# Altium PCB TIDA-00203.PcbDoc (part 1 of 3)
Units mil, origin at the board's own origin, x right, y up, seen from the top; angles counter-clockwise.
Board outline 2000 x 3000 mil, 4 copper layers (TOP LAYER, L2_GND-PLANE, L3_PWR-PLANE, BOTTOM LAYER), stack 90 mil thick; 187 components, 138 nets, 683 pads, 415 vias.
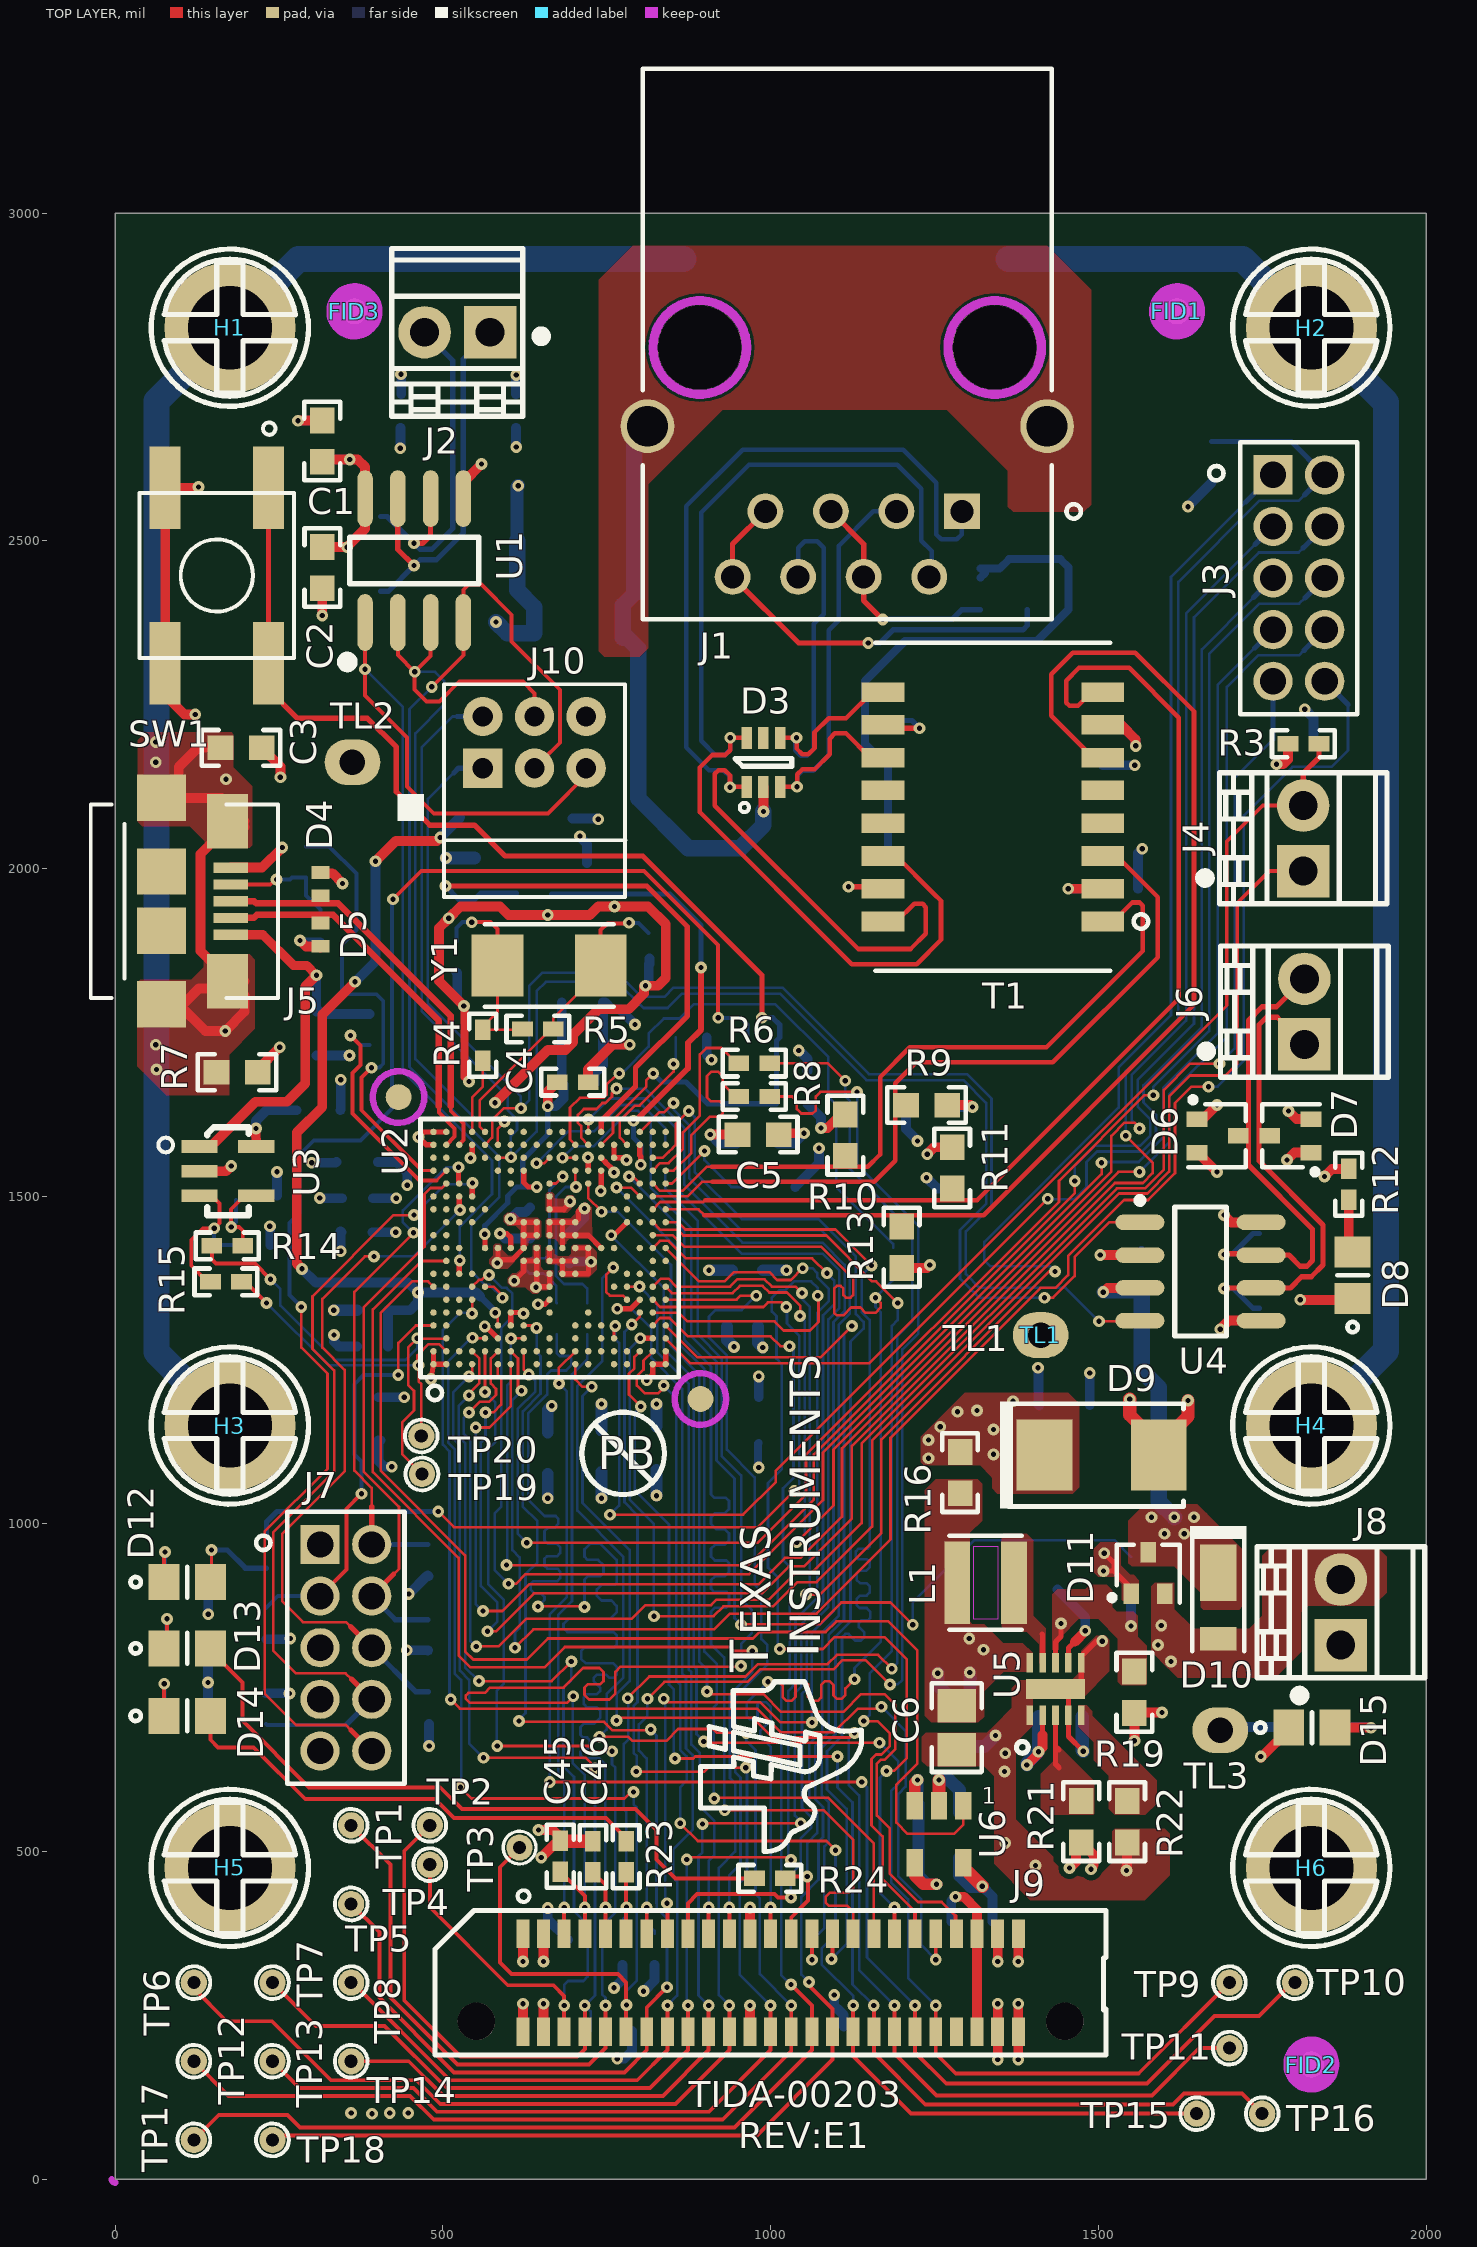
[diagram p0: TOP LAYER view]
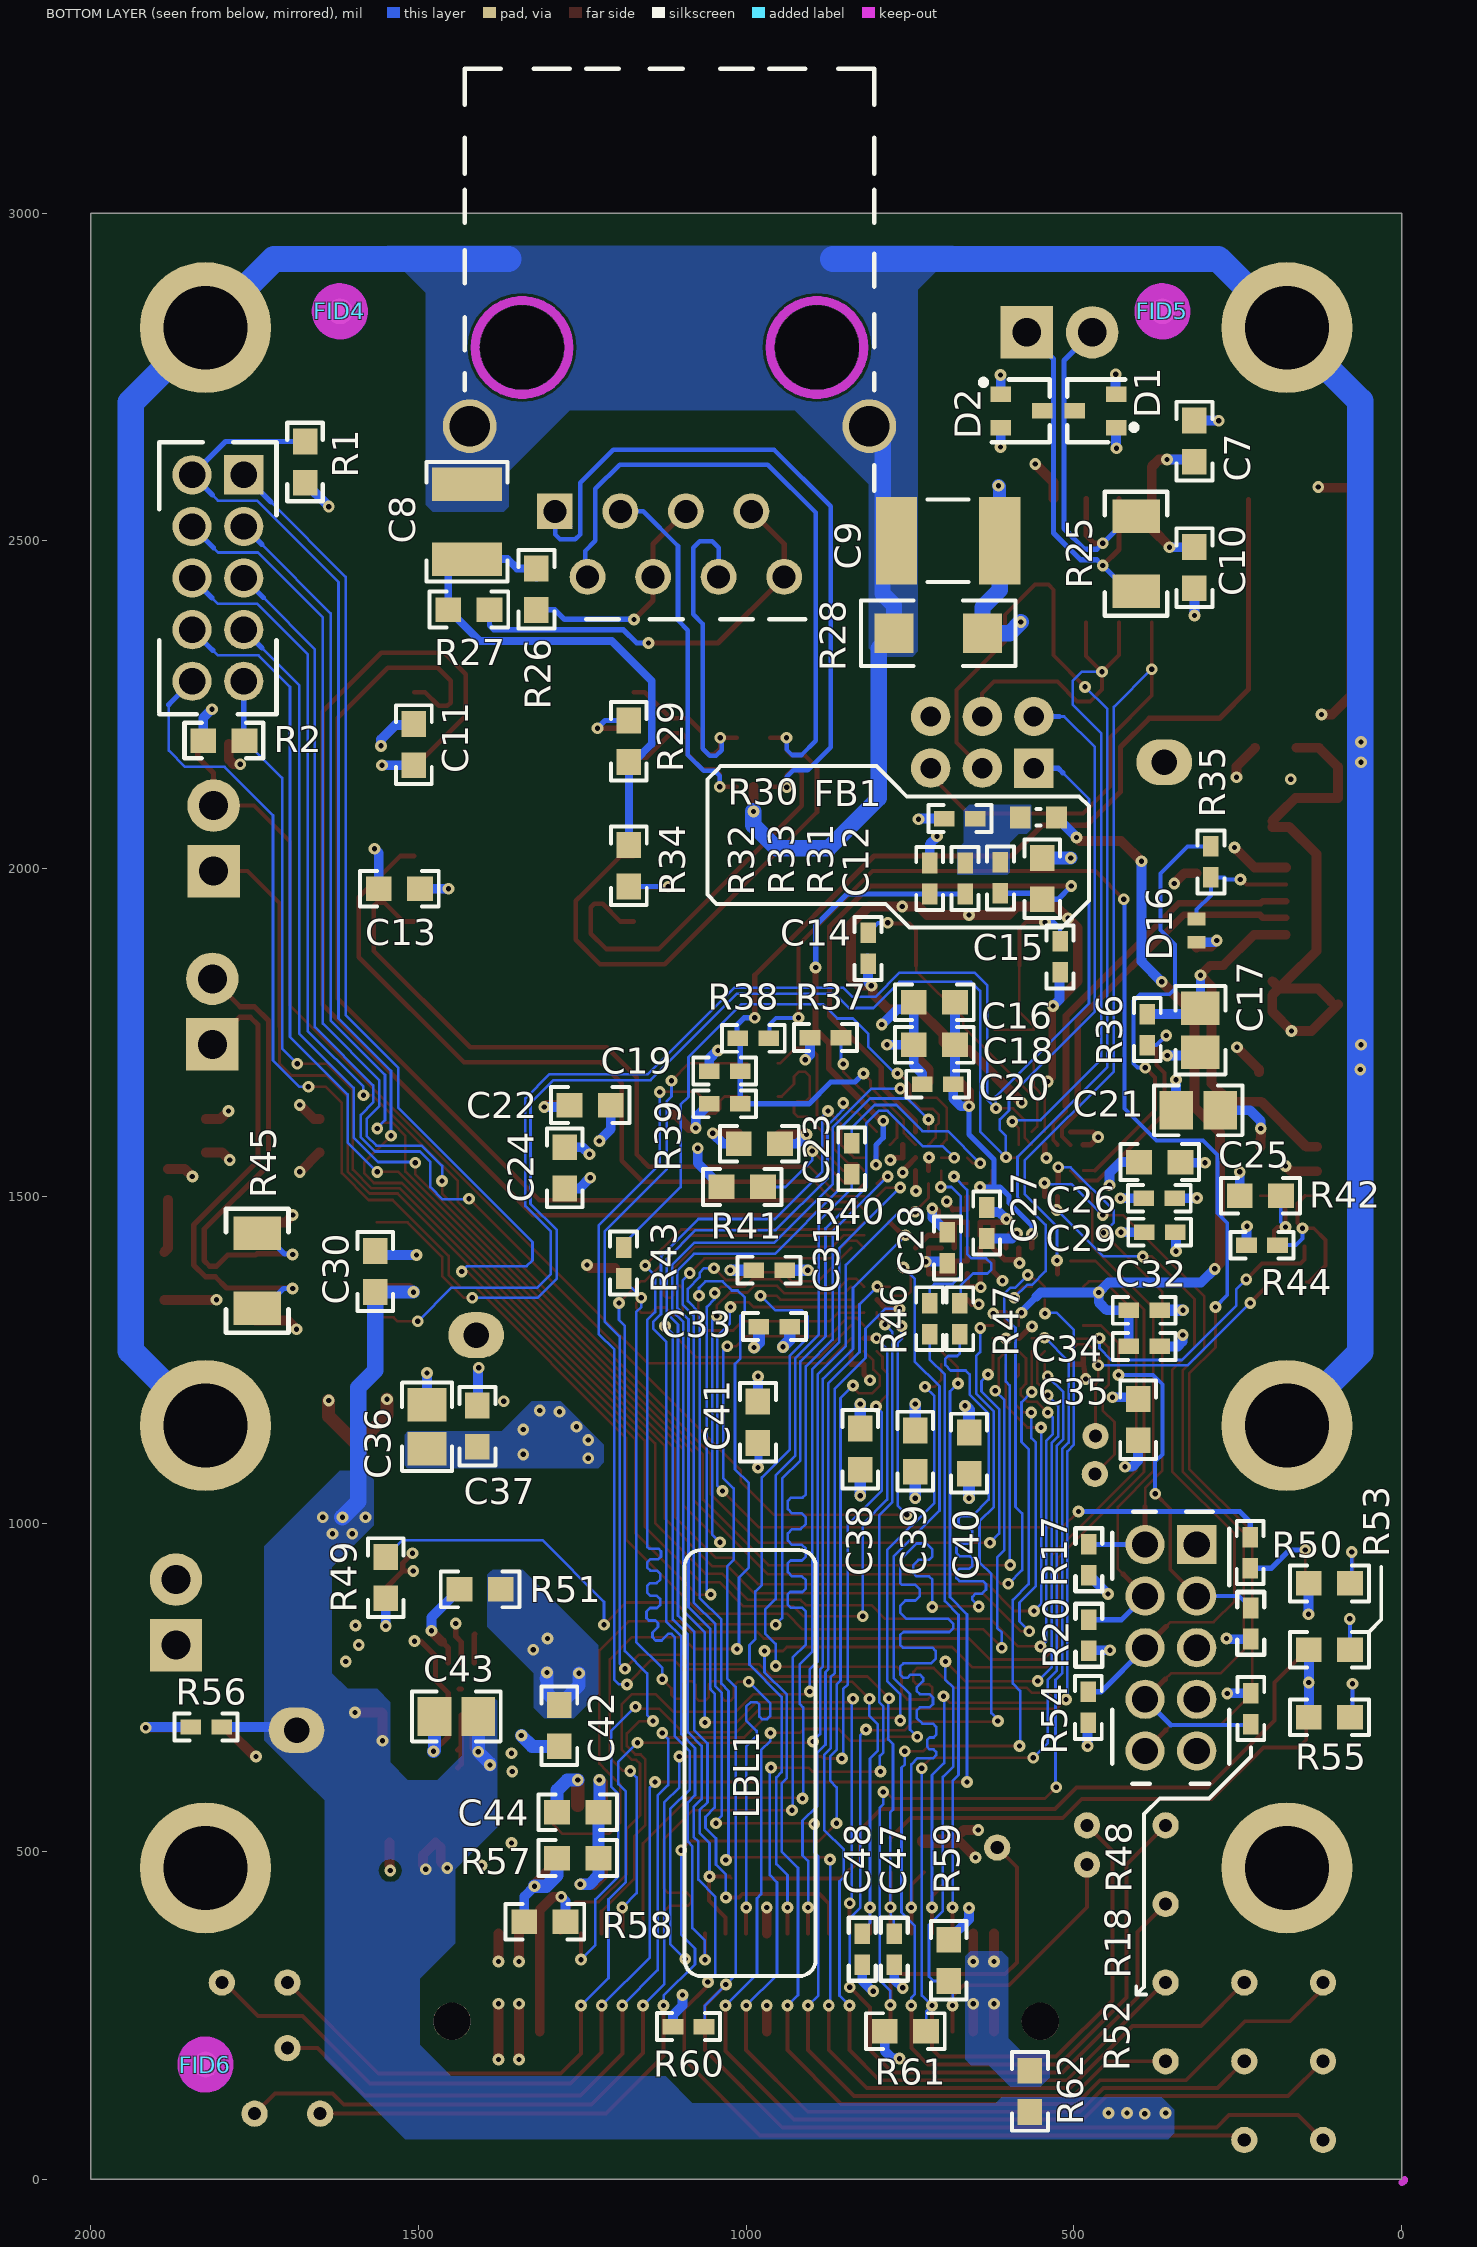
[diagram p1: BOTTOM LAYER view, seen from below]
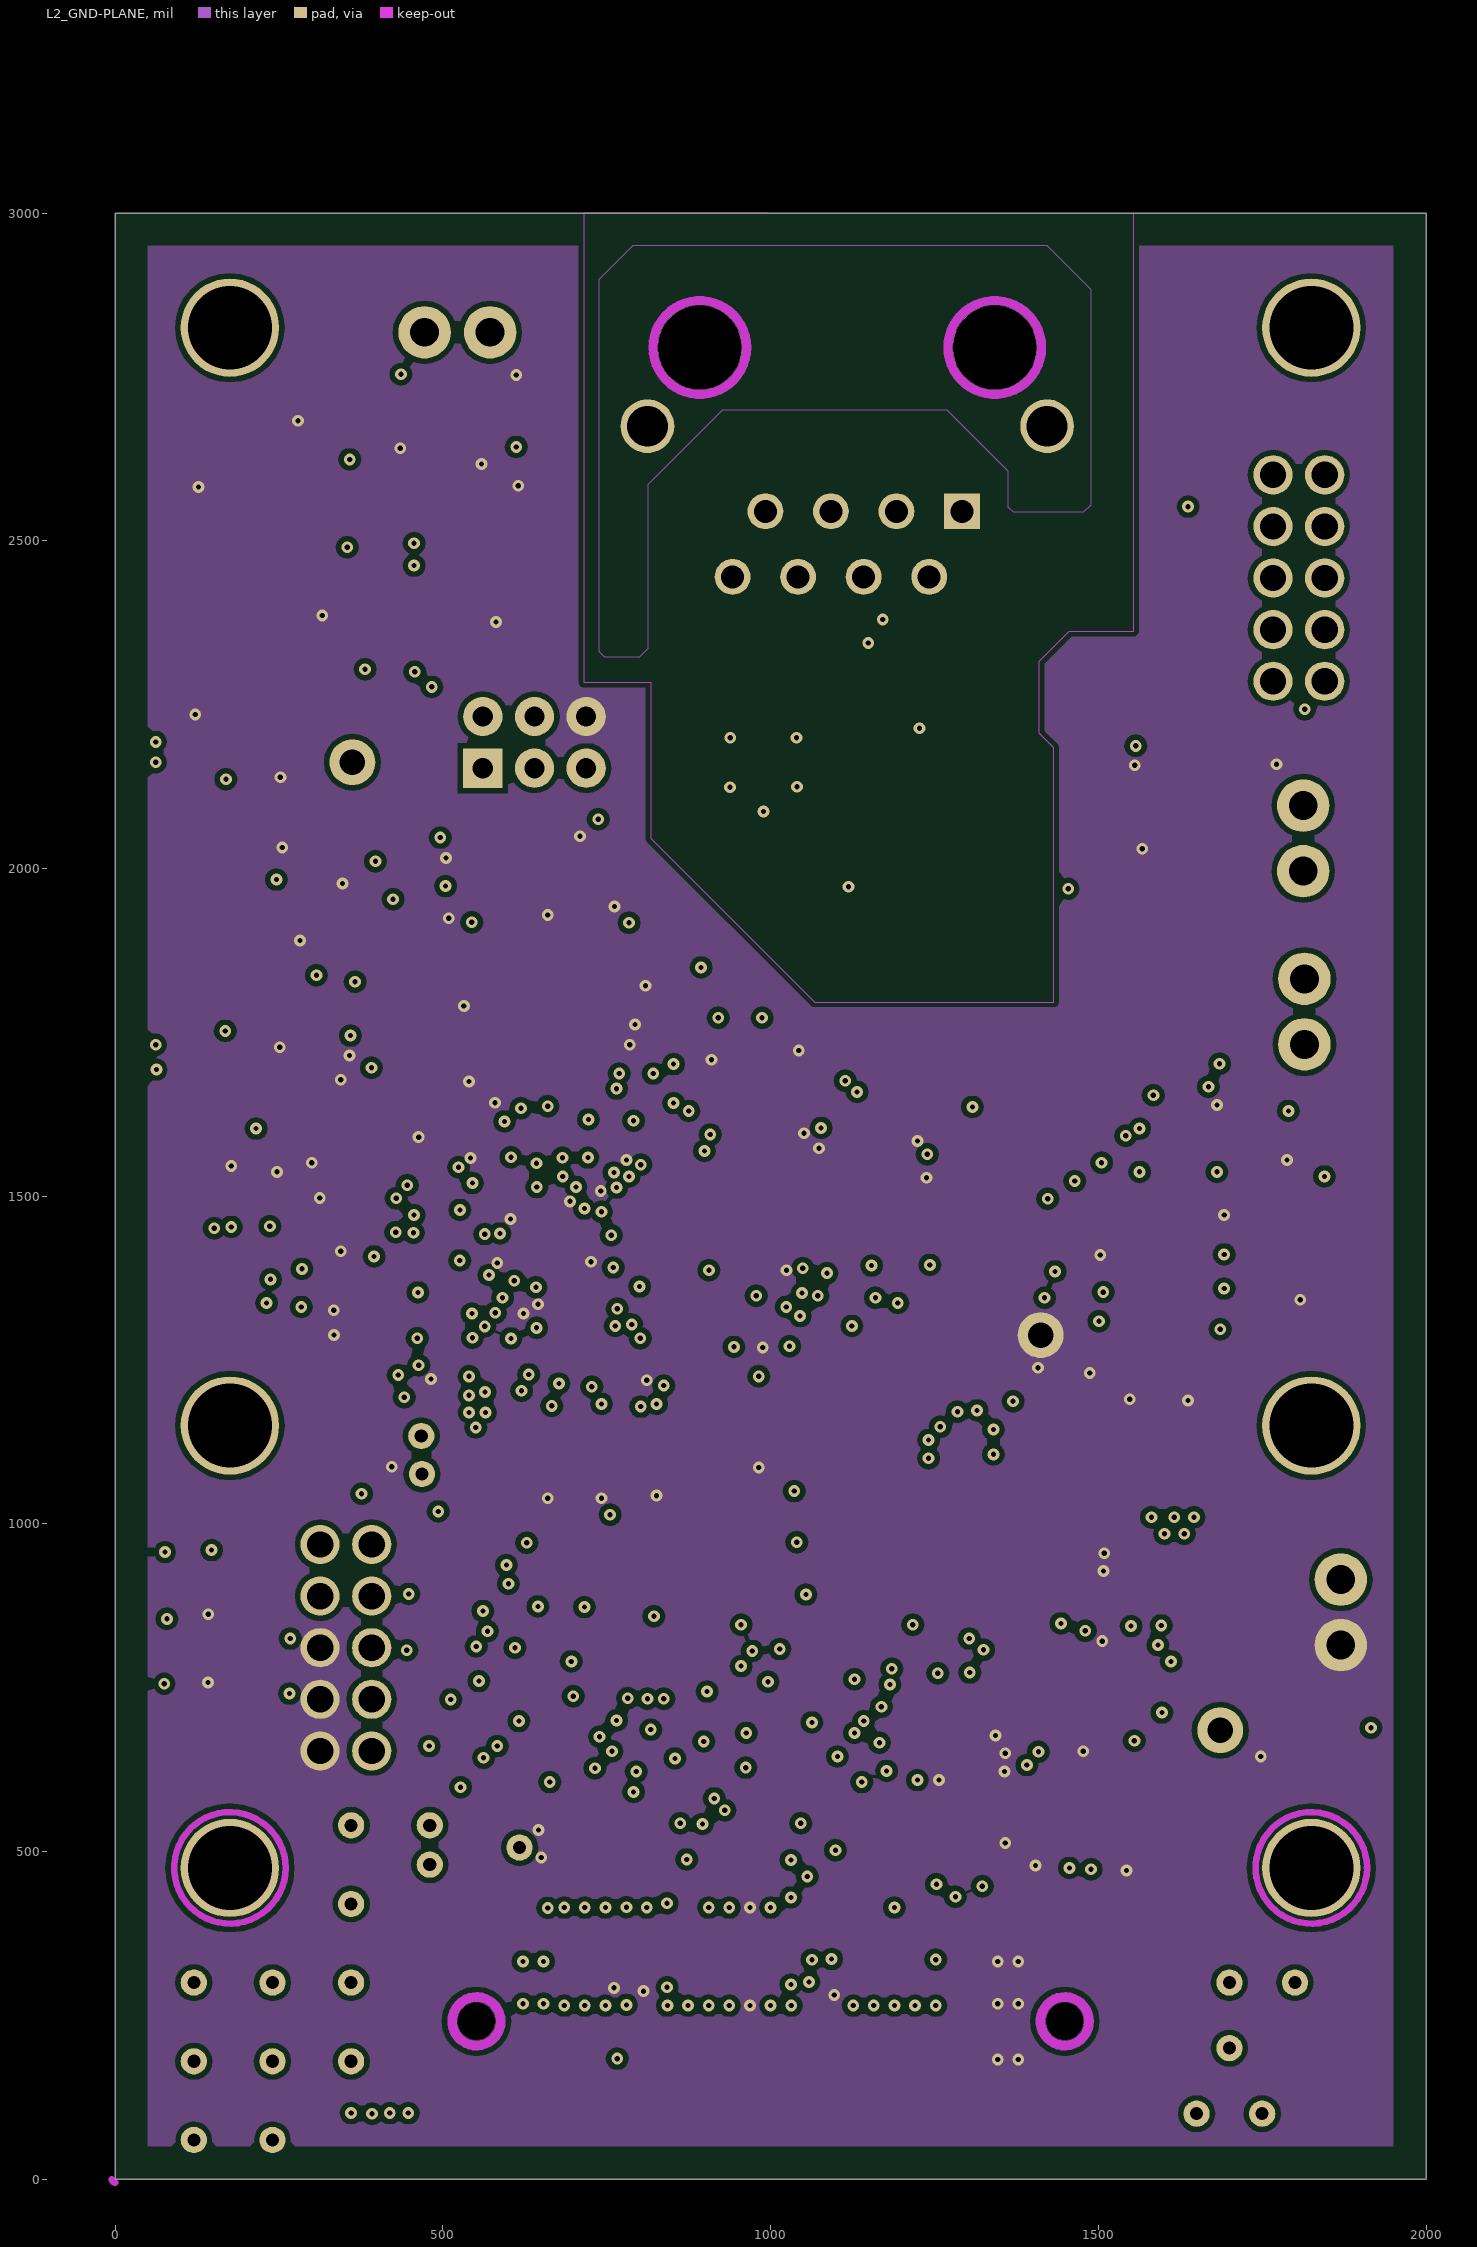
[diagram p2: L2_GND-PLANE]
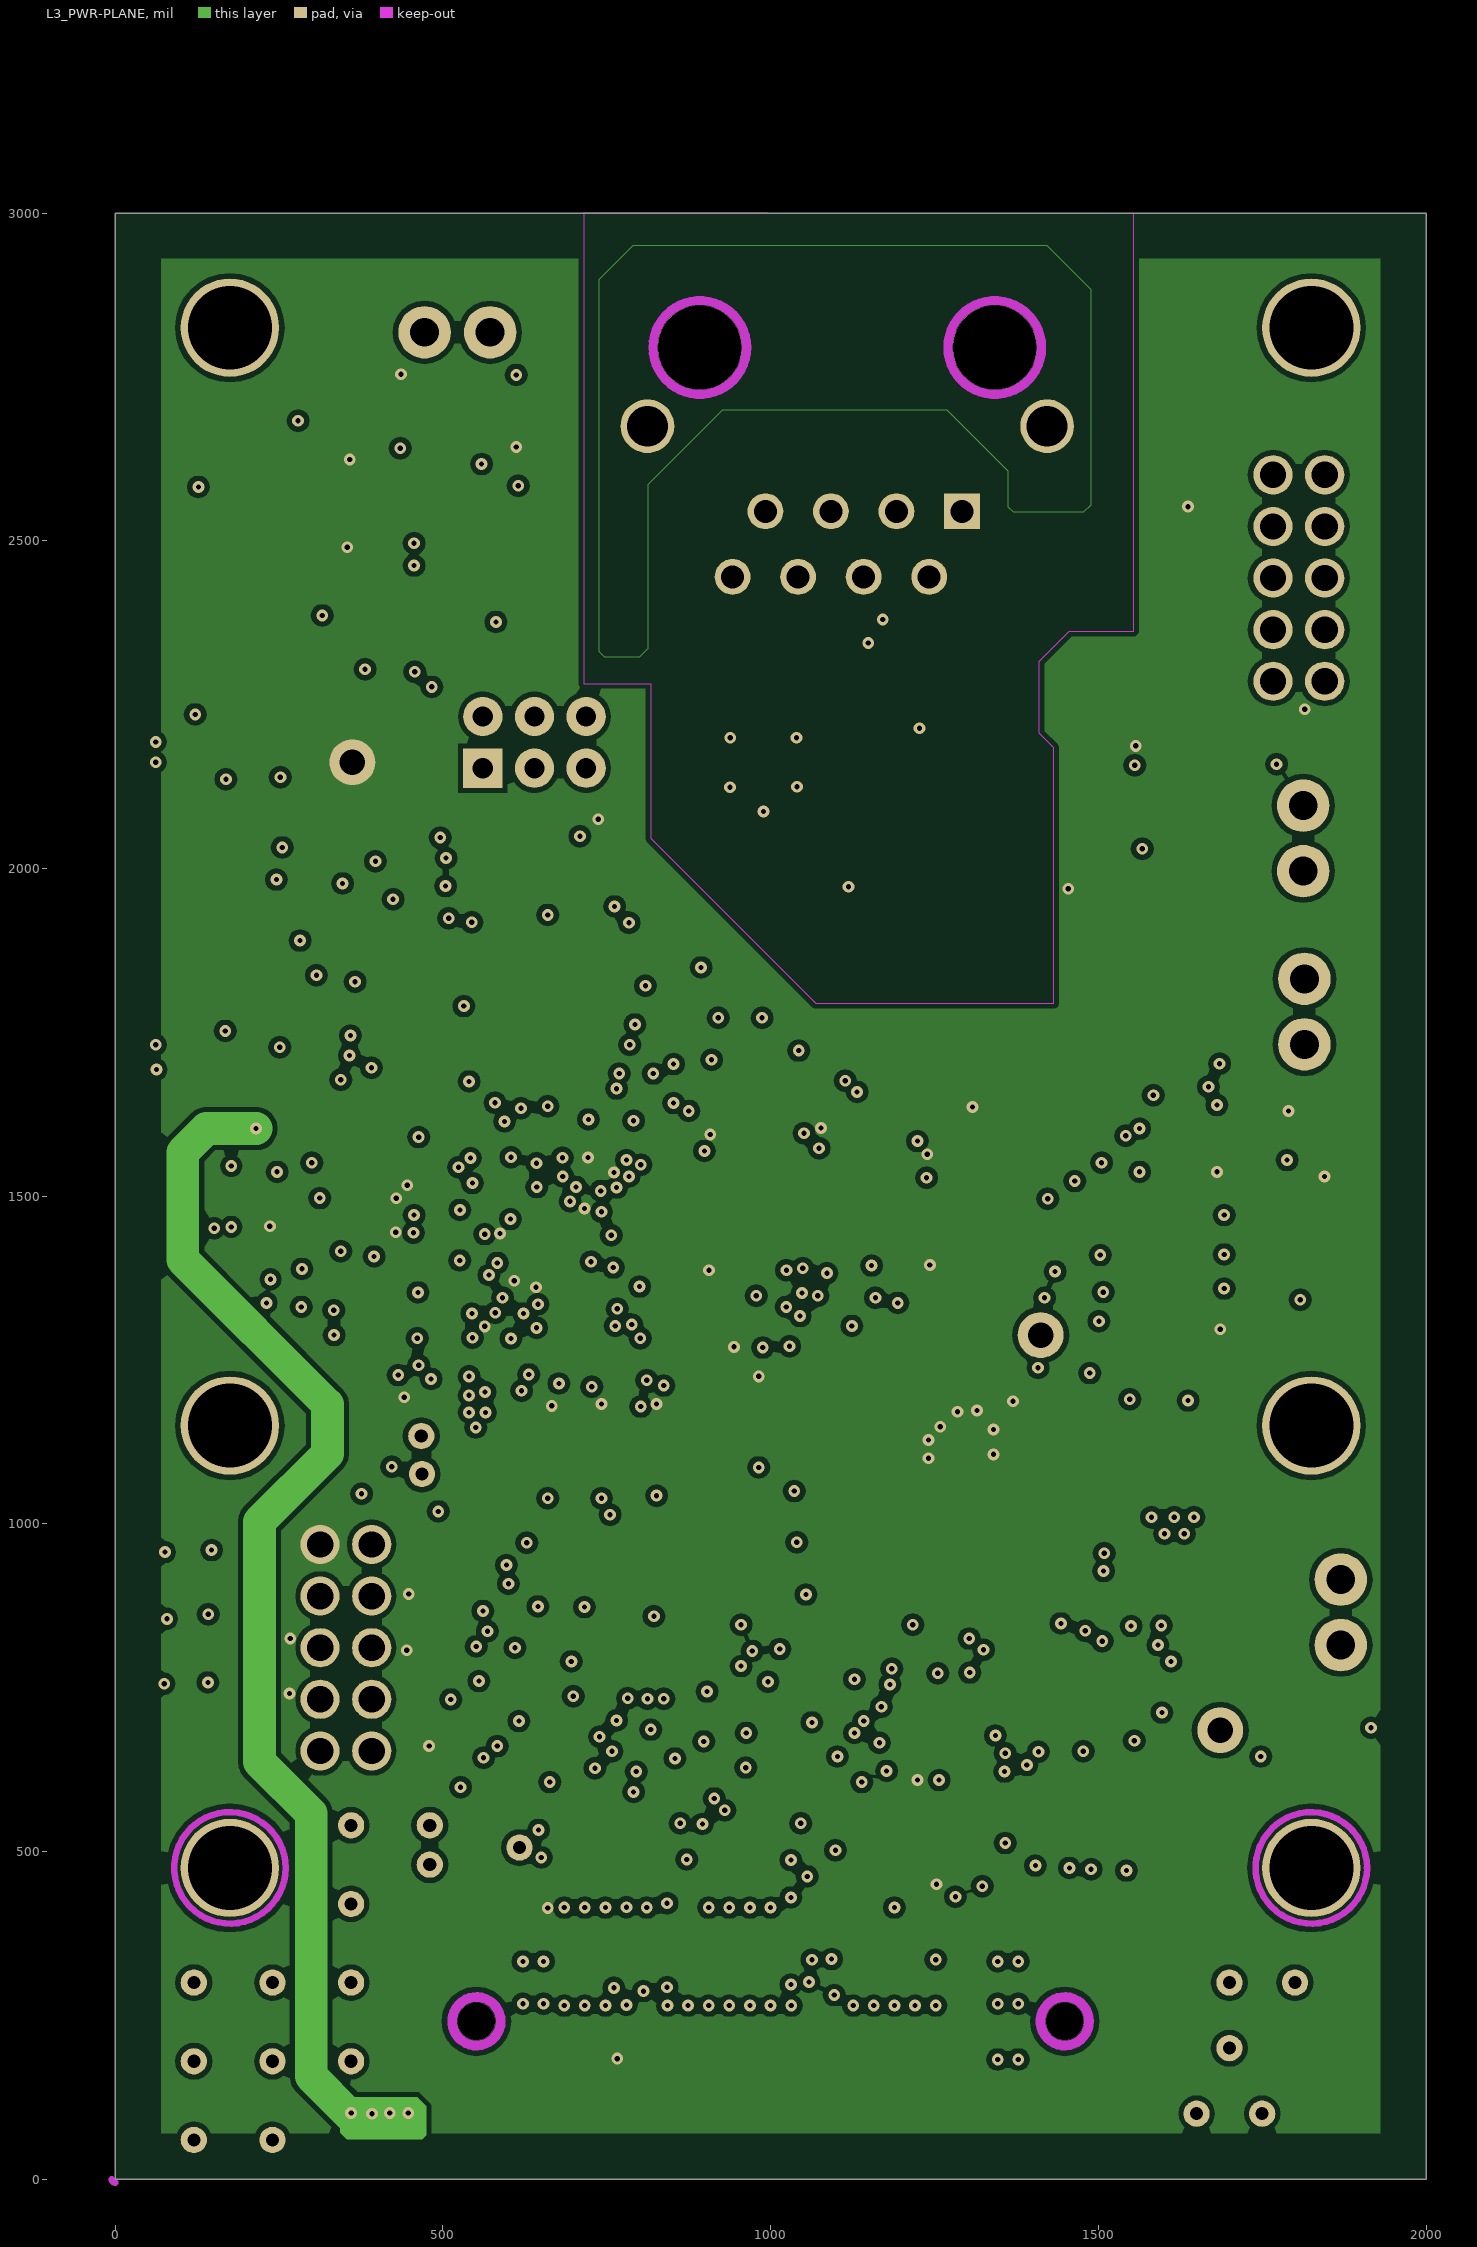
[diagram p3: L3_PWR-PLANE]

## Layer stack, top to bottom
TOP LAYER: signal copper 1.4
Dielectric: core 59.2, FR-4, Dk 4.8
L2_GND-PLANE: signal copper 1.4
Dielectric: prepreg 12.6, FR-4, Dk 4.8
L3_PWR-PLANE: signal copper 1.4
Dielectric: core 12.6, FR-4, Dk 4.8
BOTTOM LAYER: signal copper 1.4

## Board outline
0,0 2000,0 2000,3000 0,3000 0,0

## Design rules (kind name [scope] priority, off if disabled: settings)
Clearance L3 [OnLayer('L3_PWR-PLANE')] p1: gap=8
Clearance L2 [OnLayer('L2_GND-PLANE')] p2: gap=8
Clearance 5v [InNet('+5V')] p3: gap=8
Clearance Clearance_J4 [InPolygon vs InPadClass('J4-J6')] p4: gap=6
Clearance [All] p5: gap=4
Clearance DIFF_ETH [InNet('TX+_RJ45') vs InNet('TX-_RJ45')] p6: gap=16
Clearance "TRACE TO VIA" [IsVia vs IsTrack] p7: gap=4
Clearance "VIA TO TH PIN" [IsThruPin vs IsVia] p8: gap=10
Clearance "TRACE TO TRACE" [IsTrack vs IsTrack] p9: gap=4
Clearance "VIA TO VIA" [IsVia vs IsVia] p10: gap=8
Clearance "VIA 2 SMT PIN" [IsVia vs IsSMTPin] p11: gap=8
ComponentClearance "'Default' PADS rule_12" [All] p1: gap=6 collisioncheckmode=3 verticalgap=10 showdistances=FALSE
DiffPairsRouting DiffPair_ENO_TXDiffPairsRouting [InDifferentialPair ('EN0_TX')] p1: maxlimit=16 minlimit=16 mostfreqgap=16 maxuncoupledlength=500
DiffPairsRouting DiffPair_EN0_RXDiffPairsRouting [InDifferentialPair ('EN0_RX')] p2: maxlimit=16 minlimit=16 mostfreqgap=16 maxuncoupledlength=500
DiffPairsRouting DiffPair_RX_RJ45DiffPairsRouting [InDifferentialPair ('RX_RJ45')] p3: maxlimit=16 minlimit=16 mostfreqgap=16 maxuncoupledlength=500
DiffPairsRouting DiffPair_TX_RJ45DiffPairsRouting [InDifferentialPair ('TX_RJ45')] p4: maxlimit=16 minlimit=16 mostfreqgap=16 maxuncoupledlength=500
DiffPairsRouting [InDifferentialPair ('TX_RJ45')] p5: maxlimit=10 minlimit=10 mostfreqgap=10 maxuncoupledlength=500
DiffPairsRouting DiffPair_ETH_RXDiffPairsRouting [InDifferentialPair ('ETH_RX')] p6: maxlimit=16 minlimit=16 mostfreqgap=16 maxuncoupledlength=500
DiffPairsRouting DiffPair_ETHRX1DiffPairsRouting [InDifferentialPair ('ETH_RX')] p7: maxlimit=16 minlimit=16 mostfreqgap=16 maxuncoupledlength=500
DiffPairsRouting DiffPair_USB0DiffPairsRouting [InDifferentialPair ('USB0')] p8: maxlimit=7.5 minlimit=7.5 mostfreqgap=7.5 maxuncoupledlength=500
FlightTimeFalling "'Default' PADS rule_10" [All] p1: maximum=10.00
FlightTimeRising "'Default' PADS rule_9" [All] p1: maximum=10.00
HoleSize [All] p1: absolutevalues=TRUE maxlimit=150 minlimit=1 maxpercent=80.000 minpercent=20.000
Length TX [InNetClass('TX')] p1: maxlimit=1956 minlimit=1856
Length RX [InNetClass('RX')] p2: maxlimit=1667 minlimit=1567
MatchedLengths DiffPair_ENO_TXMatchedLengths [InDifferentialPair ('EN0_TX')] p1: tolerance=1000 checknetsindiffpair=TRUE checkdiffpairvsdiffpair=TRUE checkothers=TRUE
MatchedLengths DiffPair_EN0_RXMatchedLengths [InDifferentialPair ('EN0_RX')] p2: tolerance=1000 checknetsindiffpair=TRUE checkdiffpairvsdiffpair=TRUE checkothers=TRUE
MatchedLengths DiffPair_RX_RJ45MatchedLengths [InDifferentialPair ('RX_RJ45')] p3: tolerance=1000 checknetsindiffpair=TRUE checkdiffpairvsdiffpair=TRUE checkothers=TRUE
MatchedLengths DiffPair_TX_RJ45MatchedLengths [InDifferentialPair ('TX_RJ45')] p4: tolerance=1000 checknetsindiffpair=TRUE checkdiffpairvsdiffpair=TRUE checkothers=TRUE
MatchedLengths [InDifferentialPair ('TX_RJ45')] p5: tolerance=1000 checknetsindiffpair=TRUE checkdiffpairvsdiffpair=TRUE checkothers=TRUE
MaxMinImpedance "'Default' PADS rule_8" [All] p1: minimum=50.00 maximum=150.0
ParallelSegment "'Default' PADS rule_7" [All] p1: limit=1000 gap=200
ParallelSegment "'Default' PADS rule_6" [All] p2: limit=1000 gap=200
PlaneClearance "'Net' PADS rule_20" [InNet('GND')] p1: clearance=10
PlaneClearance "'Default' PADS rule_14" [All] p2: clearance=10
PlaneConnect "Power Plane Connect Style - pads with no thermal" [(Name='A1-1') Or (Name='A2-1') Or (Name='A3-1') Or (Name='A4-1') Or (Name='A5-1') Or (Name='A6-1') Or (Name='A7-1') Or (Name='A8-1') Or (Name='J15-5') Or (Name='J15-6') Or (Name='J19-21') Or (Name='J19-22') Or (Name='J27-2') Or (Name='J27-4') Or (Name='J28-2') Or (Name='J30-B4') Or (Name='J31-21') Or (Name='J31-22') Or (Name='J32-11') Or (Name='J32-12') Or (Name='J38-11') Or (Name='J38-12') Or (Name='J38-13')] p1: planeconnectstyle=NoConnect reliefexpansion=20 reliefentries=4 reliefconductorwidth=10 reliefairgap=10 // PAD - No Thermal Connect Rule
PlaneConnect "Power Plane Connect Style - from global settings" [All] p2: planeconnectstyle=Relief reliefexpansion=20 reliefentries=2 reliefconductorwidth=8 reliefairgap=10
PolygonConnect PolygonConnect_16 [All] p1: connectstyle=Direct reliefconductorwidth=10 reliefentries=4 polygonreliefangle="90 Angle" airgapwidth=10
PolygonConnect PolygonConnect_15 [All] p2: connectstyle=Direct reliefconductorwidth=10 reliefentries=4 polygonreliefangle="90 Angle" airgapwidth=10
PolygonConnect PolygonConnect_14 [All vs IsNamedPolygon('Bottom Layer-No Net 1')] p3: connectstyle=Direct reliefconductorwidth=10 reliefentries=4 polygonreliefangle="90 Angle" airgapwidth=10
PolygonConnect PolygonConnect_13 [All vs IsNamedPolygon('Top Layer-No Net 2')] p4: connectstyle=Direct reliefconductorwidth=10 reliefentries=4 polygonreliefangle="90 Angle" airgapwidth=10
PolygonConnect PolygonConnect_12 [All vs IsNamedPolygon('Top Layer-No Net 2')] p5: connectstyle=Direct reliefconductorwidth=10 reliefentries=4 polygonreliefangle="90 Angle" airgapwidth=10
PolygonConnect PolygonConnect_11 [All vs IsNamedPolygon('Bottom Layer-No Net 2')] p6: connectstyle=Direct reliefconductorwidth=10 reliefentries=4 polygonreliefangle="90 Angle" airgapwidth=10
PolygonConnect PolygonConnect_10 [All vs IsNamedPolygon('Bottom Layer-No Net 2')] p7: connectstyle=Direct reliefconductorwidth=10 reliefentries=4 polygonreliefangle="90 Angle" airgapwidth=10
PolygonConnect PolygonConnect_9 [All vs IsNamedPolygon('Bottom Layer-No Net 2')] p8: connectstyle=Direct reliefconductorwidth=10 reliefentries=4 polygonreliefangle="90 Angle" airgapwidth=10
PolygonConnect PolygonConnect_8 [All vs IsNamedPolygon('Top Layer-No Net 2')] p9: connectstyle=Direct reliefconductorwidth=10 reliefentries=4 polygonreliefangle="90 Angle" airgapwidth=10
PolygonConnect PolygonConnect_6 [All vs IsNamedPolygon('Top Layer-No Net 1')] p10: connectstyle=Direct reliefconductorwidth=10 reliefentries=4 polygonreliefangle="90 Angle" airgapwidth=10
PolygonConnect PolygonConnect_5 [All vs IsNamedPolygon('Top Layer-No Net')] p11: connectstyle=Direct reliefconductorwidth=10 reliefentries=4 polygonreliefangle="90 Angle" airgapwidth=10
PolygonConnect PolygonConnect_4 [All vs IsNamedPolygon('Bottom Layer-No Net 1')] p12: connectstyle=Direct reliefconductorwidth=10 reliefentries=4 polygonreliefangle="90 Angle" airgapwidth=10
PolygonConnect PolygonConnect_3 [All vs IsNamedPolygon('Bottom Layer-No Net')] p13: connectstyle=Direct reliefconductorwidth=10 reliefentries=4 polygonreliefangle="90 Angle" airgapwidth=10
PolygonConnect PolygonConnect_2 [All vs IsNamedPolygon('Bottom Layer-No Net')] p14: connectstyle=Direct reliefconductorwidth=10 reliefentries=4 polygonreliefangle="90 Angle" airgapwidth=10
PolygonConnect PolygonConnect_1 [All vs IsNamedPolygon('Bottom Layer-No Net')] p15: connectstyle=Direct reliefconductorwidth=10 reliefentries=4 polygonreliefangle="90 Angle" airgapwidth=10
PolygonConnect [All] p16: connectstyle=Relief reliefconductorwidth=10 reliefentries=4 polygonreliefangle="90 Angle" airgapwidth=10
RoutingVias [All] p1: holewidth=8 width=18 viastyle="Through Hole" minholewidth=8 minwidth=18 maxholewidth=8 maxwidth=18
SMDToCorner [All] p1: distance=40000
SMDToPlane [All] p1: distance=40000
SilkscreenOverComponentPads [All] p1: minsilkscreentomaskgap=10
SolderMaskExpansion [All] p1: expansion=2
Width DiffPair_ENO_TXWidth [InDifferentialPair('EN0_TX')] p1: maxlimit=7 minlimit=4 preferedwidth=7
Width DiffPair_EN0_RXWidth [InDifferentialPair('EN0_RX')] p2: maxlimit=7 minlimit=4 preferedwidth=7
Width DiffPair_RX_RJ45Width [InDifferentialPair('RX_RJ45')] p3: maxlimit=7 minlimit=4 preferedwidth=7
Width DiffPair_TX_RJ45Width [InDifferentialPair('TX_RJ45')] p4: maxlimit=7 minlimit=4 preferedwidth=7
Width Width_3 [InDifferentialPair('TX_RJ45')] p5: maxlimit=10 minlimit=10 preferedwidth=10
Width DiffPair_ETH_RXWidth [InDifferentialPair('ETH_RX')] p6: maxlimit=7 minlimit=7 preferedwidth=7
Width DiffPair_ETHRX1Width [InDifferentialPair('ETH_RX')] p7: maxlimit=7 minlimit=7 preferedwidth=7
Width DiffPair_USB0Width [InDifferentialPair('USB0')] p8: maxlimit=10 minlimit=10 preferedwidth=10
Width Width_2 [InNet('GND')] p9: maxlimit=50 minlimit=8 preferedwidth=15
Width Width_1 [InNet('3.3V')] p10: maxlimit=25 minlimit=8 preferedwidth=15
Width [All] p11: maxlimit=100 minlimit=4 preferedwidth=4
22 further rules are at their usual default settings.

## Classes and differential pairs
component class Pg4_10_100_ETHERNET_USB: C3 C8 C9 C11 C13 C17 C21 C22 C24 D3 D4 D5 D12 D13 D14 D16 J1 J5 R7 R9 R10 R11 R13 R14 R15 R23 R24 R26 R27 R28 R29 R34 R35 R36 R41 R42 R44 R48 R50 R53 R55 T1 TP19 TP20 U3
pad class J4-J6: J2-1 J2-2 J4-1 J4-2 J6-1 J6-2 R42-1 R42-2 R44-1 R44-2
net class TX_U-C: NetR6_1 NetR8_1 NetR40_1 NetR47_1
component class Label: LBL1
component class AssemblyNote: ZZ1 ZZ2 ZZ3 ZZ4
component class Pg9_Hardware_ANSI-B: FID1 FID2 FID3 FID4 FID5 FID6 H1 H2 H3 H4 H5 H6 LBL1 ZZ1 ZZ2 ZZ3 ZZ4
component class Pg5_CAN_RS485: C1 C2 C7 C10 C30 D1 D2 D6 D7 J2 J6 J10 R25 R45 U1 U4
component class FiducialMark: FID1 FID2 FID3 FID4 FID5 FID6
component class "Mounting Holes": H1 H2 H3 H4 H5 H6
component class Pg7_POWER_SUPPLY: C6 C36 C37 C42 C43 C101 D8 D9 D15 L1 R12 R16 R19 R21 R22 R49 R51 R56 TL1 TL2 TL3 U5
component class Pg6_MII_RMII_INTERFACE: C44 D10 D11 J8 J9 R57 R58 R62 TP1 TP2 TP3 TP4 TP5 TP6 TP7 TP8 TP9 TP10 TP11 TP12 TP13 TP14 TP15 TP16 TP17 TP18 U6
component class Pg3_MICROCONTROLLER: C4 C5 C12 C14 C15 C16 C18 C19 C20 C23 C25 C26 C27 C28 C29 C31 C32 C33 C34 C35 C38 C39 C40 C41 C45 C46 C47 C48 FB1 R1 R2 R3 R4 R5 R6 R8 R30 R31 R32 R33 R37 R38 R39 R40 R43 R46 R47 R59 R60 R61 R97 SW1 U2 Y1
component class Pg8_SPARE_AND_DEBUG: J3 J4 J7 R17 R18 R20 R52 R54
net class TX: TX_CLK TXD0 TXD1 TXD2 TXD3
net class RX: RX_CLK RXD0 RXD1 RXD2 RXD3
differential pair TX_RJ45: +TX+_RJ45 -TX-_RJ45
differential pair RX_RJ45: +RX+_RJ45 -RX-_RJ45
differential pair EN0_RX: +EN0RX+ -EN0RX-
differential pair EN0_TX: +EN0TX+ -EN0TX-

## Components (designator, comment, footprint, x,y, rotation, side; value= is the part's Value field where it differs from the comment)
C1 "C0603C106M9PACTU" 0603 316,2652 r90 top (schematic designator C93)
C2 "GRM188R61C104KA01D" 0603 316,2459 r270 top (schematic designator C95)
C3 "CAPC0603" 0603 192,2184 r180 top (schematic designator C30)
C4 "CAPC0603" 0402 698,1674 r0 top (schematic designator C61)
C5 "CAPC0603" 0603 981,1594 r0 top (schematic designator C39)
C6 "CAPC0805" 0805 1284,689 r270 top (schematic designator C2)
C7 "GRM188R61C104KA01D" 0603 316,2652 r90 bottom (schematic designator C94)
C8 "CAPC1210" 1210 1426,2529 r90 bottom (schematic designator C90)
C9 "CAPC0603" 1812 692,2500 r180 bottom (schematic designator C38)
C10 "GRM188R61C104KA01D" 0603 316,2459 r270 bottom (schematic designator C96)
C11 "CAPC0603" 0603 1507,2189 r270 bottom (schematic designator C66)
C12 "CAPC0603" 0603 548.21,1984.34 r90 bottom (schematic designator C70)
C13 "CAPC0603" 0603 1529,1969 r0 bottom (schematic designator C40)
C14 "GRM1555C1H330JA01D" 0402 814,1878 r90 bottom (schematic designator C25)
C15 "GRM1555C1H330JA01D" 0402 521,1865 r270 bottom (schematic designator C23)
C16 "CAPC0603" 0603 712.72,1795.79 r0 bottom (schematic designator C53)
C17 "CAPC0805" 0805 307,1753 r270 bottom
C18 "CAPC0603" 0603 712.72,1730.79 r0 bottom (schematic designator C55)
C19 "CAPC0402" 0402 1032.72,1690.79 r0 bottom (schematic designator C99)
C20 "CAPC0402" 0402 707.72,1670.79 r0 bottom (schematic designator C57)
C21 "CAPC0805" 0805 310,1631 r0 bottom (schematic designator C19)
C22 "CAPC0603" 0603 1238,1639 r180 bottom (schematic designator C62)
C23 "CAPC0603" 0603 979.72,1579.79 r0 bottom (schematic designator C16)
C24 "CAPC0603" 0603 1277,1543 r270 bottom (schematic designator C65)
C25 "CAPC0603" 0603 369,1552 r180 bottom (schematic designator C54)
C26 "CAPC0402" 0402 369.72,1496.79 r180 bottom (schematic designator C59)
C27 "CAPC0603" 0402 633,1459 r90 bottom (schematic designator C63)
C28 "CAPC0603" 0402 693,1421 r270 bottom (schematic designator C64)
C29 "CAPC0402" 0402 369,1445 r180 bottom (schematic designator C60)
C30 "06033C104JAT2A" 0603 1566,1385 r270 bottom (schematic designator C91)
C31 "CAPC0402" 0402 965,1387 r0 bottom (schematic designator C22)
C32 "CAPC0402" 0402 392.72,1325.79 r180 bottom (schematic designator C18)
C33 "CAPC0402" 0402 957,1301 r0 bottom (schematic designator C56)
C34 "CAPC0402" 0402 392.72,1270.79 r180 bottom (schematic designator C58)
C35 "CAPC0603" 0603 402,1159 r270 bottom (schematic designator C29)
C36 "CAPC0805" 0805 1487,1148 r90 bottom (schematic designator C101)
C37 "CAPC0603" 0603 1410,1149 r90 bottom (schematic designator C102)
C38 "CAPC0603" 0603 826,1114 r270 bottom (schematic designator C28)
C39 "CAPC0603" 0603 742,1111 r270 bottom (schematic designator C33)
C40 "CAPC0603" 0603 660,1108 r270 bottom (schematic designator C52)
C41 "CAPC0603" 0603 982,1155 r270 bottom (schematic designator C67)
C42 "CAPC0603" 0603 1285,692 r270 bottom (schematic designator C100)
C43 "CAPC0805" 0805 1442.1,706.1 r0 bottom (schematic designator C4)
C44 "06033C104JAT2A" 0603 1257,560 r0 bottom (schematic designator C92)
C45 "GRM1555C1H330JA01D" 0402 679,493 r270 top
C46 "GRM1555C1H330JA01D" 0402 729,492 r270 top
C47 "GRM1555C1H330JA01D" 0402 774,351 r90 bottom
C48 "GRM1555C1H330JA01D" 0402 823,351 r90 bottom
D1 "DESD1P0RFW-7" SOT-323 467,2698 r0 bottom (schematic designator D21)
D2 "DESD1P0RFW-7" SOT-323 580,2698 r180 bottom (schematic designator D20)
D3 "TPD4E1U06DCK" DCK0006A_N 989,2161.91 r90 top
D4 "B72590D0050H160" RESC0402N 313,1976 r90 top (schematic designator D6)
D5 "B72590D0050H160" RESC0402N 313,1899 r270 top
D6 "DESD1P0RFW-7" SOT-323 1682,1592 r0 top (schematic designator D18)
D7 "DESD1P0RFW-7" SOT-323 1793,1592 r180 top (schematic designator D19)
D8 "LED-0805" DIOC0805N 1888,1379 r90 top (schematic designator D10)
D9 "1SMB5915BT3G" SMB 1505,1105 r0 top (schematic designator D23)
D10 "DFLS1200-7" powerDI123 1683,875 r270 top (schematic designator D17)
D11 "DESD1P0RFW-7" SOT-323 1576,925 r90 top (schematic designator D22)
D12 "LED-0805" DIOC0805N 110,911 r0 top (schematic designator D8)
D13 "LED-0805" DIOC0805N 110,810 r0 top (schematic designator D16)
D14 "LED-0805" DIOC0805N 110,707 r0 top (schematic designator D15)
D15 "LED-0805" DIOC0805N 1826,689 r0 top (schematic designator D9)
D16 "B72590D0050H160" RESC0402N 313,1905 r270 bottom (schematic designator D7)
FB1 "1000 OHM" 0603L 554,2078 r180 bottom
FID1 "Fiducial" Fiducial10-20 1620,2850 r90 top
FID2 "Fiducial" Fiducial10-20 1825,175 r0 top
FID3 "Fiducial" Fiducial10-20 365,2850 r0 top
FID4 "Fiducial" Fiducial10-20 1620,2850 r180 bottom (schematic designator FID3)
FID5 "Fiducial" Fiducial10-20 365,2850 r180 bottom (schematic designator FID1)
FID6 "Fiducial" Fiducial10-20 1825,175 r180 bottom (schematic designator FID2)
H1 "NY PMS 440 0025 PH" MH3.2_H5_W6_KO8_STARHEAD#1 175,2825 r0 top locked
H2 "NY PMS 440 0025 PH" MH3.2_H5_W6_KO8_STARHEAD#2 1825,2825 r0 top locked
H3 "NY PMS 440 0025 PH" MH3.2_H5_W6_KO8_STARHEAD#2 175,1150 r0 top locked (schematic designator H13)
H4 "NY PMS 440 0025 PH" MH3.2_H5_W6_KO8_STARHEAD#2 1825,1150 r0 top locked (schematic designator H14)
H5 "NY PMS 440 0025 PH" MH3.2_H5_W6_KO8_STARHEAD#2 175,475 r0 top locked (schematic designator H3)
H6 "NY PMS 440 0025 PH" MH3.2_H5_W6_KO8_STARHEAD#2 1825,475 r0 top locked (schematic designator H4)
J1 "RJ45_NOMAG_NOLED" TE_6116526-1 1117,2800 r180 top locked
J2 "CON-OSTVN02A150" CN2_MTB_P100_PD80_D1.1_S5.54X6.5_STACK 522,2818 r180 top (schematic designator J38)
J3 "HEADER_2041501" "HDR2X5 _2MM" 1806,2443 r0 top
J4 "CON-OSTVN02A150" CN2_MTB_P100_PD80_D1.1_S5.54X6.5_STACK 1812.68,2045.92 r90 top (schematic designator J35)
J5 "ZX62R-AB-5P" CON-USB-MICRO-REV 71,1950 r0 top (schematic designator J24)
J6 "CON-OSTVN02A150" CN2_MTB_P100_PD80_D1.1_S5.54X6.5_STACK 1814.49,1781.49 r90 top (schematic designator J37)
J7 "HEADER_2041501" "HDR2X5 _2MM" 352,811 r0 top
J8 "CON-OSTVN02A150" CN2_MTB_P100_PD80_D1.1_S5.54X6.5_STACK 1870,865 r90 top (schematic designator J36)
J9 "ERM8-025-05.0-L-DV-K-TR" SAMTEC_ERM8-025-05_0-L-DV-K-TR 1000,300 r0 top locked (schematic designator J40)
J10 "HEADER_TMM-103-01-G-D-RA" HEADER_TMM-103[2X] 561,2153 r0 top
L1 "IND-WE-7440" IND_744029100 1328,910 r180 top
LBL1 "Size: 0.65\" x 0.20 \"" Label_650x200 994,635 r90 bottom
R1 "RESC0603" 0603 1673,2620 r90 bottom (schematic designator R91)
R2 "RESC0603" 0603 1797,2195 r180 bottom (schematic designator R87)
R3 "CRCW04022K20JNED" 0402 1813,2190 r0 top (schematic designator R94)
R4 "RESC0402" 0402 561,1730 r270 top (schematic designator R33)
R5 "CRCW04021M00JNED" 0402 645,1755 r180 top (schematic designator R92)
R6 "RESC0402" 0402 975,1703 r0 top (schematic designator R81)
R7 "RESC0603" 0603 186,1689 r0 top (schematic designator R36)
R8 "RESC0402" 0402 975,1652 r0 top (schematic designator R82)
R9 "RESC0603" 0603 1238,1639 r180 top (schematic designator R41)
R10 "RESC0603" 0603 1114,1593 r270 top (schematic designator R42)
R11 "RESC0603" 0603 1277,1543 r270 top (schematic designator R37)
R12 "RESC0402" 0402 1882,1518 r270 top (schematic designator R49)
R13 "RESC0603" 0603 1200,1422 r90 top (schematic designator R40)
R14 "CRCW040233R0JNED" 0402 171,1424 r180 top (schematic designator R85)
R15 "CRCW040233R0JNED" 0402 169,1369 r0 top (schematic designator R86)
R16 "RESC0603" 0603 1289,1078 r90 top (schematic designator R20)
R17 "RESC0402" 0402 477,945 r90 bottom (schematic designator R71)
R18 "RESC0402" 0402 230,848 r90 bottom (schematic designator R21)
R19 "RESC0603" 0603 1555,743 r90 top (schematic designator R2)
R20 "RESC0402" 0402 477,830 r90 bottom (schematic designator R72)
R21 "RESC0603" 0603 1474,545.5 r90 top (schematic designator R14)
R22 "RESC0603" 0603 1544,545.5 r270 top (schematic designator R8)
R23 "RESC0402" 0402 779.53,492 r90 top (schematic designator R99)
R24 "RESC0402" 0402 999,459 r180 top (schematic designator R98)
R25 "RC1206FR-07120RL" 1206#1 405,2480 r90 bottom (schematic designator R70)
R26 "RESC0603" 0603 1320,2426 r270 bottom (schematic designator R66)
R27 "RESC0603" 0603 1423,2395 r180 bottom (schematic designator R67)
R28 "RESC1206" 1206#2 707,2359 r180 bottom (schematic designator R44)
R29 "RESC0603" 0603 1179,2194 r90 bottom (schematic designator R64)
R30 "RESC0402" 0402 674,2076 r0 bottom (schematic designator R90)
R31 "RESC0402" 0402 612,1985.62 r90 bottom (schematic designator R63)
R32 "RESC0402" 0402 720,1984.62 r90 bottom (schematic designator R96)
R33 "RESC0402" 0402 666,1984.62 r270 bottom (schematic designator R39)
R34 "RESC0603" 0603 1179,2004 r270 bottom (schematic designator R65)
R35 "CRCW040233R0JNED" 0402 291,2010 r90 bottom (schematic designator R83)
R36 "CRCW040233R0JNED" 0402 388,1754 r270 bottom (schematic designator R84)
R37 "RESC0402" 0402 879,1742 r180 bottom (schematic designator R93)
R38 "RESC0402" 0402 989.09,1740.79 r180 bottom (schematic designator R97)
R39 "RESC0402" 0402 1032.72,1640.79 r180 bottom (schematic designator R34)
R40 "RESC0402" 0402 839,1557 r270 bottom (schematic designator R79)
R41 "RESC0603" 0603 1006,1514 r0 bottom (schematic designator R38)
R42 "RESC0603" 0603 215.3,1500.6 r180 bottom (schematic designator R31)
R43 "CRCW040233R0JNED" 0402 1187,1398 r270 bottom (schematic designator R75)
R44 "RESC0402" 0402 213,1425 r0 bottom (schematic designator R27)
R45 "RC1206FR-07120RL" 1206#1 1746,1386 r90 bottom (schematic designator R68)
R46 "CRCW040233R0JNED" 0402 720,1313 r270 bottom (schematic designator R78)
R47 "RESC0402" 0402 674,1313 r270 bottom (schematic designator R80)
R48 "RESC0402" 0402 231,956 r270 bottom (schematic designator R100)
R49 "RESC0603" 0603 1550,918 r270 bottom (schematic designator R16)
R50 "RESC0603" 0603 110,909 r0 bottom (schematic designator R45)
R51 "RESC0603" 0603 1406,900 r0 bottom (schematic designator R1)
R52 "RESC0402" 0402 230,718 r270 bottom (schematic designator R74)
R53 "RESC0603" 0603 110,808 r0 bottom (schematic designator R46)
R54 "RESC0402" 0402 478,720 r90 bottom (schematic designator R73)
R55 "RESC0603" 0603 110,705 r0 bottom (schematic designator R47)
R56 "RESC0402" 0402 1824,690 r0 bottom (schematic designator R48)
R57 "ERJ-3RSFR10V" 0603 1257,490 r180 bottom (schematic designator R69)
R58 "RESC0603" 0603 1307,393 r0 bottom (schematic designator R77)
R59 "RESC0603" 0603 691,334 r270 bottom (schematic designator R89)
R60 "CRCW04022K20JNED" 0402 1088,233 r180 bottom (schematic designator R95)
R61 "RESC0603" 0603 757,226 r180 bottom (schematic designator R88)
R62 "RESC0603" 0603 567,134 r90 bottom (schematic designator R76)
SW1 "SW-EVQQ2" SW-EVQQ2 155,2447 r270 top
T1 "HX1198FNL" "XFMR_ HX1198FNL" 1339,2094 r180 top locked
TL1 "TESTLOOP-100" PAD70H39 1412,1288 r270 top (schematic designator TL6)
TL2 "TESTLOOP-100" PAD70H39 362,2162 r270 top (schematic designator TL3)
TL3 "TESTLOOP-100" PAD70H39 1686,685 r270 top (schematic designator TL2)
TP1 "TP1_PD40_D0.5_S50" TP1_PD40_D0.5_S50 360,540 r90 top (schematic designator TP16)
TP2 "TP1_PD40_D0.5_S50" TP1_PD40_D0.5_S50 480,540 r90 top (schematic designator TP17)
TP3 "TP1_PD40_D0.5_S50" TP1_PD40_D0.5_S50 617,506 r90 top (schematic designator TP15)
TP4 "TP1_PD40_D0.5_S50" TP1_PD40_D0.5_S50 480,480 r90 top (schematic designator TP18)
TP5 "TP1_PD40_D0.5_S50" TP1_PD40_D0.5_S50 360,420 r90 top (schematic designator TP14)
TP6 "TP1_PD40_D0.5_S50" TP1_PD40_D0.5_S50 120,300 r90 top (schematic designator TP10)
TP7 "TP1_PD40_D0.5_S50" TP1_PD40_D0.5_S50 240,300 r90 top (schematic designator TP12)
TP8 "TP1_PD40_D0.5_S50" TP1_PD40_D0.5_S50 360,300 r90 top (schematic designator TP13)
TP9 "TP1_PD40_D0.5_S50" TP1_PD40_D0.5_S50 1700,300 r0 top (schematic designator TP1)
TP10 "TP1_PD40_D0.5_S50" TP1_PD40_D0.5_S50 1800,300 r90 top (schematic designator TP2)
TP11 "TP1_PD40_D0.5_S50" TP1_PD40_D0.5_S50 1700,200 r90 top (schematic designator TP3)
TP12 "TP1_PD40_D0.5_S50" TP1_PD40_D0.5_S50 120,180 r90 top (schematic designator TP8)
TP13 "TP1_PD40_D0.5_S50" TP1_PD40_D0.5_S50 240,180 r90 top (schematic designator TP9)
TP14 "TP1_PD40_D0.5_S50" TP1_PD40_D0.5_S50 360,180 r90 top (schematic designator TP11)
TP15 "TP1_PD40_D0.5_S50" TP1_PD40_D0.5_S50 1650,100 r90 top (schematic designator TP5)
TP16 "TP1_PD40_D0.5_S50" TP1_PD40_D0.5_S50 1750,100 r90 top (schematic designator TP4)
TP17 "TP1_PD40_D0.5_S50" TP1_PD40_D0.5_S50 120,60 r90 top (schematic designator TP7)
TP18 "TP1_PD40_D0.5_S50" TP1_PD40_D0.5_S50 240,60 r90 top (schematic designator TP6)
TP19 "TP1_PD40_D0.5_S50" TP1_PD40_D0.5_S50 468,1076 r90 top
TP20 "TP1_PD40_D0.5_S50" TP1_PD40_D0.5_S50 467,1134 r90 top
U1 "SN65HVD72DR" D0008A_N 456.22,2469.79 r90 top (schematic designator U10)
U2 "TM4C129X" BGA212C50P19X19_1000X1000X100 662.72,1420.79 r90 top (schematic designator U1)
U3 "TPS2051B" DBV5 172,1538 r0 top (schematic designator U5)
U4 "SN65HVD256D" D0008A_L 1656,1385 r0 top (schematic designator U12)
U5 "TPS62177DQC" DQC-10P 1434.7,748 r0 top (schematic designator U7)
U6 "INA196AIDBVR" SOT23-5P 1257,525 r270 top (schematic designator U8)
Y1 "XTAL-NX5032GA" XTAL-NX5032GA 662,1852 r180 top (schematic designator Y2)
ZZ1 "These assemblies must be clean and free from flux and all contaminants. Use of no clean flux is not acceptable." AssemblyNote 386,4089 r0 top (schematic designator ZZ3)
ZZ2 "These assemblies must comply with workmanship standards IPC-A-610 Class 2, unless otherwise specified." AssemblyNote 386,3984 r0 top (schematic designator ZZ4)
ZZ3 "These assemblies are ESD sensitive, ESD precautions shall be observed." AssemblyNote -603,3122 r0 top (schematic designator ZZ2)
ZZ4 "This Assembly Note is for PCB labels only" AssemblyNoteLabel -692,3003 r0 top (schematic designator ZZ1)

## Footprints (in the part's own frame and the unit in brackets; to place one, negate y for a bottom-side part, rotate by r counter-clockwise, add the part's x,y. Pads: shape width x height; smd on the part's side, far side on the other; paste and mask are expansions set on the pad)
0402 [mm] "0402 from SM-752 data"
  rect 0.8x0.6 smd: 1(-0.6,0) 2(0.6,0)
  silkscreen extent -1.22,-0.52 1.22,0.52, body extent -0.55,-0.3 0.55,0.3, height 0.6
0603 [mm] "0603 from SM-752 data"
  rect 1x0.95 smd: 1(-0.8,0) 2(0.8,0)
  silkscreen extent -1.52,-0.69 1.52,0.69, body extent -0.87,-0.47 0.87,0.47, height 0.85
0603L [mm] "0603 from SM-752 data"
  rect 0.8x0.85 smd: 1(-0.7,0) 2(0.7,0)
  silkscreen extent -0.07,-0.33 0.07,0.33, body extent -0.87,-0.47 0.87,0.47, height 0.85
0805 [mm] "0805 from SM-752 data"
  rect 1.3x1.5 smd: 1(-0.85,0) 2(0.85,0)
  silkscreen extent -1.72,-0.97 1.72,0.97, body extent -1.1,-0.72 1.1,0.72, height 1.1
1206#1 [mm] "1206 from SM-752 data"
  rect 1.3x1.85 smd: 1(-1.45,0) 2(1.45,0)
  silkscreen extent -2.4,-1.21 2.4,1.21, body extent -1.7,-0.9 1.7,0.9, height 1.35
1206#2 [mm]
  rect 1.524x1.524 smd: 1(-1.714,0) 2(1.714,0)
  silkscreen extent -3,-1.27 3,1.27
1210 [mm] "1210 from SM-752 data"
  rect 1.3x2.7 smd: 1(-1.45,0) 2(1.45,0)
  silkscreen extent -2.32,-1.57 2.32,1.57, body extent -1.7,-1.35 1.7,1.35, height 1.35
1812 [mm]
  rect 1.6x3.4 smd: 1(-2,0) 2(2,0)
  silkscreen extent -0.8,-1.6 0.8,1.6, body extent -2.4,-1.7 2.4,1.7, height 1.35
AssemblyNote [mil] "Assembly Note"
AssemblyNoteLabel [mil] "Assembly Note for PCB Labels"
BGA212C50P19X19_1000X1000X100 [mm]
  round 0.25 smd mask+0: A1(-4.5,4.5) A2(-4,4.5) A4(-3,4.5) A5(-2.5,4.5) A7(-1.5,4.5) A8(-1,4.5) A10(0,4.5) A11(0.5,4.5) A13(1.5,4.5) A14(2,4.5) A16(3,4.5) A17(3.5,4.5) A18(4,4.5) A19(4.5,4.5) B1(-4.5,4) B2(-4,4) B3(-3.5,4) B4(-3,4) B5(-2.5,4) B6(-2,4) B7(-1.5,4) B8(-1,4) B9(-0.5,4) B10(0,4) B11(0.5,4) B12(1,4) B13(1.5,4) B14(2,4) B15(2.5,4) B16(3,4) B17(3.5,4) B18(4,4) B19(4.5,4) C1(-4.5,3.5) C2(-4,3.5) C5(-2.5,3.5) C6(-2,3.5) C8(-1,3.5) C10(0,3.5) C12(1,3.5) C14(2,3.5) C15(2.5,3.5) C18(4,3.5) D1(-4.5,3) D2(-4,3) D6(-2,3) D7(-1.5,3) D8(-1,3) D12(1,3) D13(1.5,3) D14(2,3) D18(4,3) D19(4.5,3) E2(-4,2.5) E3(-3.5,2.5) E7(-1.5,2.5) E10(0,2.5) E13(1.5,2.5) E17(3.5,2.5) E18(4,2.5) E19(4.5,2.5) F1(-4.5,2) F2(-4,2) F3(-3.5,2) F4(-3,2) F10(0,2) F16(3,2) F17(3.5,2) F18(4,2) G1(-4.5,1.5) G2(-4,1.5) G4(-3,1.5) G5(-2.5,1.5) G10(0,1.5) G15(2.5,1.5) G16(3,1.5) G18(4,1.5) G19(4.5,1.5) H2(-4,1) H3(-3.5,1) H4(-3,1) H9(-0.5,1) H10(0,1) H11(0.5,1) H12(1,1) H16(3,1) H17(3.5,1) H18(4,1) H19(4.5,1) J1(-4.5,0.5) J2(-4,0.5) J8(-1,0.5) J9(-0.5,0.5) J10(0,0.5) J11(0.5,0.5) J12(1,0.5) J18(4,0.5) K1(-4.5,0) K2(-4,0) K3(-3.5,0) K5(-2.5,0) K6(-2,0) K7(-1.5,0) K8(-1,0) K9(-0.5,0) K10(0,0) K11(0.5,0) K12(1,0) K13(1.5,0) K14(2,0) K15(2.5,0) K17(3.5,0) K18(4,0) K19(4.5,0) L2(-4,-0.5) L8(-1,-0.5) L9(-0.5,-0.5) L10(0,-0.5) L11(0.5,-0.5) L12(1,-0.5) L18(4,-0.5) L19(4.5,-0.5) M1(-4.5,-1) M2(-4,-1) M3(-3.5,-1) M4(-3,-1) M8(-1,-1) M9(-0.5,-1) M10(0,-1) M11(0.5,-1) M12(1,-1) M16(3,-1) M17(3.5,-1) M18(4,-1) N1(-4.5,-1.5) N2(-4,-1.5) N4(-3,-1.5) N5(-2.5,-1.5) N10(0,-1.5) N15(2.5,-1.5) N16(3,-1.5) N18(4,-1.5) N19(4.5,-1.5) P2(-4,-2) P3(-3.5,-2) P4(-3,-2) P10(0,-2) P16(3,-2) P17(3.5,-2) P18(4,-2) P19(4.5,-2) R1(-4.5,-2.5) R2(-4,-2.5) R3(-3.5,-2.5) R7(-1.5,-2.5) R10(0,-2.5) R13(1.5,-2.5) R17(3.5,-2.5) R18(4,-2.5) T1(-4.5,-3) T2(-4,-3) T6(-2,-3) T7(-1.5,-3) T8(-1,-3) T12(1,-3) T13(1.5,-3) T14(2,-3) T18(4,-3) T19(4.5,-3) U2(-4,-3.5) U5(-2.5,-3.5) U6(-2,-3.5) U8(-1,-3.5) U10(0,-3.5) U12(1,-3.5) U14(2,-3.5) U15(2.5,-3.5) U18(4,-3.5) U19(4.5,-3.5) V1(-4.5,-4) V2(-4,-4) V3(-3.5,-4) V4(-3,-4) V5(-2.5,-4) V6(-2,-4) V7(-1.5,-4) V8(-1,-4) V9(-0.5,-4) V10(0,-4) V11(0.5,-4) V12(1,-4) V13(1.5,-4) V14(2,-4) V15(2.5,-4) V16(3,-4) V17(3.5,-4) V18(4,-4) V19(4.5,-4) W1(-4.5,-4.5) W2(-4,-4.5) W3(-3.5,-4.5) W4(-3,-4.5) W6(-2,-4.5) W7(-1.5,-4.5) W9(-0.5,-4.5) W10(0,-4.5) W12(1,-4.5) W13(1.5,-4.5) W15(2.5,-4.5) W16(3,-4.5) W18(4,-4.5) W19(4.5,-4.5)
  round 1 smd paste-25.4 mask+0.5: FID1(-5.85,-5.85) FID2(5.85,5.85)
  TOP LAYER keep-out circle w0.254: c5.85,5.85 r1
  TOP LAYER keep-out circle w0.254: c-5.85,-5.85 r1
  silkscreen extent -5.89,-5 5,5, body extent -5,-5 5,5, height 1
CN2_MTB_P100_PD80_D1.1_S5.54X6.5_STACK [mil]
  rect 80x80 / inner round 80 / far side rect 80x80 hole 44: 1(-50,0)
  round 80 hole 44: 2(50,0)
  silkscreen extent -138,-128 100,128
CON-USB-MICRO-REV [mm]
  rect 1.35x0.4 smd: 1(2.675,-1.3) 2(2.675,-0.65) 3(2.675,0) 4(2.675,0.65) 5(2.675,1.3)
  rect 1.6x2.1 smd: 6(2.55,3.1) 7(2.55,-3.1)
  rect 1.9x1.8 smd: 8(0,4) 9(0,-4) 10(0,1.15) 11(0,-1.15)
  silkscreen extent -2.75,-3.75 4.5,3.75
D0008A_L [mm] "SOIC, 8-Leads, Body 4.9x3.9mm, Pitch 1.27mm, IPC High Density"
  oval 1.9x0.6 smd: 1(-2.35,1.905) 2(-2.35,0.635) 3(-2.35,-0.635) 4(-2.35,-1.905) 5(2.35,-1.905) 6(2.35,-0.635) 7(2.35,0.635) 8(2.35,1.905)
  silkscreen extent -2.47,-2.5 1,2.88, body extent -2,-2.5 2,2.5, height 1.75
D0008A_N [mm] "SOIC, 8-Leads, Body 4.9x3.9mm, Pitch 1.27mm, IPC Medium Density"
  oval 2.2x0.6 smd: 1(-2.4,1.905) 2(-2.4,0.635) 3(-2.4,-0.635) 4(-2.4,-1.905) 5(2.4,-1.905) 6(2.4,-0.635) 7(2.4,0.635) 8(2.4,1.905)
  silkscreen extent -4.13,-2.5 0.9,2.79, body extent -2,-2.5 2,2.5, height 1.75
DBV5 [mil]
  rect 55.1x19.7 smd: 1(-43.3,37.4) 2(-43.3,0) 3(-43.3,-37.4) 4(43.3,-37.4) 5(43.3,37.4)
  silkscreen extent -106,-67 32,67
DCK0006A_N [mm] "SOT23, 6-Leads, Body 2x1.3mm, Pitch 0.65mm, Lead Span 2.1mm, IPC Medium Density"
  rect 0.85x0.4 smd: 1(-0.95,0.65) 2(-0.95,0) 3(-0.95,-0.65) 4(0.95,-0.65) 5(0.95,0) 6(0.95,0.65)
  silkscreen extent -0.15,-1.1 0.15,1.1, body extent -1.14,-1 1.14,1, height 0.94
DIOC0805N [mm]
  rect 1.2x1.4 smd: 1(-0.9,0) 2(0.9,0)
  silkscreen extent -2.2,-0.6 0,0.6
DQC-10P [mil]
  rect 10x30 smd mask+2: 1(-39.4,-40) 2(-19.7,-40) 3(0,-40) 4(19.7,-40) 5(39.4,-40) 6(39.4,40) 7(19.7,40) 8(0,40) 9(-19.7,40) 10(-39.4,40)
  rect 90x30 smd mask+2: 11(0,0)
  silkscreen extent -60,-98 -42,-80
Fiducial10-20 [mm]
  round 1 smd paste-0.5 mask+0.5: 1(0,0)
  TOP LAYER keep-out circle w1.178: c0,0 r0.5
"HDR2X5 _2MM" [mm] "CONN, MALE, 2 MM PITCH, 10-PIN"
  rect 1.52x1.52 / inner round 1.52 / far side rect 1.52x1.52 hole 1.02: 1(-1,4)
  round 1.52 hole 1.02: 2(1,4) 3(-1,2) 4(1,2) 5(-1,0) 6(1,0) 7(-1,-2) 8(1,-2) 9(-1,-4) 10(1,-4)
  silkscreen extent -3.48,-5.27 2.27,5.27, body extent -2.27,-5.27 2.27,5.27, height 2
HEADER_TMM-103[2X] [mil]
  rect 60x60 hole 31: 1(0,0)
  round 60 hole 31: 2(0,78.74) 3(78.74,0) 4(78.74,78.74) 5(157.48,0) 6(157.48,78.74)
  silkscreen extent -130,-80 -90,-40
IND_744029100 [mm] "INDUCTOR , SMD 2.8X2.8MM"
  rect 1x3.2 smd: 1(-1.1,0) 2(1.1,0)
  TOP LAYER keep-out region: 0.483,1.396 -0.483,1.396 -0.483,-1.404 0.483,-1.404
  M15 Courtyards Top keep-out region: 0.286,0.184 -0.294,0.184 -0.294,0.184 0.286,0.184
  silkscreen extent -1.4,-1.82 1.4,1.82, body extent -1.4,-1.4 1.4,1.4, height 1.5
Label_650x200 [mil] "Thermal Transfer Label"
  round 1 on Mech14: 0(0,0)
  silkscreen extent -325,-100 325,100, body extent -326,-101 326,101, height 1
MH3.2_H5_W6_KO8_STARHEAD#1 [mil]
  round 200 / inner round 150 / far side round 200 hole 128 paste+0 mask+40: 1(0,0)
  silkscreen extent -120,-120 120,120
MH3.2_H5_W6_KO8_STARHEAD#2 [mil]
  round 200 / inner round 150 / far side round 200 hole 128 mask+40: 1(0,0)
  silkscreen extent -120,-120 120,120
PAD70H39 [mil]
  oval 70x85 / inner round 70 / far side oval 70x85 hole 39: 1(0,0)
powerDI123 [mm] "Diodes Inc recommended land pattern, document number DS30628 Rev. 6-2"
  rect 2.2x1.4 smd: 1(-1.275,0)
  rect 0.9x1.4 smd: 2(1.275,0)
  silkscreen extent -3.1,-1.09 1.76,1.09, body extent -2.37,-0.96 1.53,0.97, height 1
RESC0402N [mm]
  rect 0.5x0.7 smd: 1(-0.45,0) 2(0.45,0)
SAMTEC_ERM8-025-05_0-L-DV-K-TR [mm] "Samtec recommended footprint"
  rect 0.5x1.1 smd: 1(-9.6,1.9) 2(-9.6,-1.9) 3(-8.8,1.9) 4(-8.8,-1.9) 5(-8,1.9) 6(-8,-1.9) 7(-7.2,1.9) 8(-7.2,-1.9) 9(-6.4,1.9) 10(-6.4,-1.9) 11(-5.6,1.9) 12(-5.6,-1.9) 13(-4.8,1.9) 14(-4.8,-1.9) 15(-4,1.9) 16(-4,-1.9) 17(-3.2,1.9) 18(-3.2,-1.9) 19(-2.4,1.9) 20(-2.4,-1.9) 21(-1.6,1.9) 22(-1.6,-1.9) 23(-0.8,1.9) 24(-0.8,-1.9) 25(0,1.9) 26(0,-1.9) 27(0.8,1.9) 28(0.8,-1.9) 29(1.6,1.9) 30(1.6,-1.9) 31(2.4,1.9) 32(2.4,-1.9) 33(3.2,1.9) 34(3.2,-1.9) 35(4,1.9) 36(4,-1.9) 37(4.8,1.9) 38(4.8,-1.9) 39(5.6,1.9) 40(5.6,-1.9) 41(6.4,1.9) 42(6.4,-1.9) 43(7.2,1.9) 44(7.2,-1.9) 45(8,1.9) 46(8,-1.9) 47(8.8,1.9) 48(8.8,-1.9) 49(9.6,1.9) 50(9.6,-1.9)
  round 1.45 hole 1.45 unplated paste+0 mask+0.127: MH1(-11.4,-1.5) MH2(11.4,-1.5)
  silkscreen extent -13,-2.8 13,2.8, body extent -13,-2.8 13,2.8, height 8.9
SMB [mil] "Molded Diode, 2-Leads, Body 5.4x3.6mm, IPC Medium Density, based on OnSemi component dimensions"
  rect 85x107.99 smd: 1(-87.01,0) 2(87.01,0)
  silkscreen extent -155,-82 125,82, body extent -106,-71 106,71, height 91
SOT23-5P [mil]
  rect 42x25 smd: 1(-45,37) 2(-45,0) 3(-45,-37) 4(42,-37) 5(42,37)
SOT-323 [mm] "Zetex recommended land pattern.  March 2007"
  rect 0.8x0.6 smd: 1(-0.8,0.65) 2(-0.8,-0.65) 3(0.8,0)
  silkscreen extent -1.58,-1.22 1.09,1.22, body extent -1.13,-1.13 1.12,1.12, height 1.13
SW-EVQQ2 [mm]
  rect 3.2x1.2 smd paste-0.025: 1(-3.4,2) 2(-3.4,-2) 3(3.4,2) 4(3.4,-2)
  silkscreen extent -3.2,-3 3.2,3
TE_6116526-1 [mm] "CONNECTOR, MODULAR JACK SHIELDED R/A, THRU-8 PIN"
  rect 1.39x1.39 hole 0.89: 1(-4.445,6.48)
  round 1.39 hole 0.89: 2(-3.175,9.02) 3(-1.905,6.48) 4(-0.635,9.02) 5(0.635,6.48) 6(1.905,9.02) 7(3.175,6.48) 8(4.445,9.02)
  round 3.25 hole 3.25 unplated mask+0.305: MH1(5.715,0.13) MH2(-5.715,0.13)
  round 2.08 hole 1.58: SH1(7.745,3.18) SH2(-7.745,3.18)
  Keep-Out Layer circle w0.178: c5.715,0.13 r1.727
  Keep-Out Layer circle w0.178: c-5.715,0.13 r1.727
  silkscreen extent -9.05,-10.67 7.93,10.67, body extent -7.94,-10.67 7.94,10.67, height 6.75
TP1_PD40_D0.5_S50 [mil]
  round 40 hole 20: 1(0,0)
  silkscreen extent -25,-25 25,25
"XFMR_ HX1198FNL" [mm] "TRANSFORMER, MODULE XFMR, 16-SOIC"
  rect 1.65x0.76 smd: 1(-4.255,4.445) 2(-4.255,3.175) 3(-4.255,1.905) 4(-4.255,0.635) 5(-4.255,-0.635) 6(-4.255,-1.905) 7(-4.255,-3.175) 8(-4.255,-4.445) 9(4.255,-4.445) 10(4.255,-3.175) 11(4.255,-1.905) 12(4.255,-0.635) 13(4.255,0.635) 14(4.255,1.905) 15(4.255,3.175) 16(4.255,4.445)
  silkscreen extent -6.02,-6.35 4.55,6.35, body extent -4.55,-6.35 4.55,6.35, height 5.99
XTAL-NX5032GA [mm]
  rect 2x2.4 smd: 1(-2,0) 2(2,0)
  silkscreen extent -2.5,-1.6 2.5,1.6

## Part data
C1: "CAP, CERM, 10uF, 6.3V, +/-20%, X5R, 0603"
C2 C7 C10: "CAP, CERM, 0.1uF, 16V, +/-10%, X5R, 0603"
C3: "Capacitor, 3300pF, 50V, 10%, X7R, 0603"
C4 C27 C28 C34: "Capacitor, 0.01uF 25V, 10% 0402 X7R"
C5 C11 C12 C13 C16 C22 C23 C24 C25 C35 C37 C38 C39 C40 C41 C42: "Capacitor, 0.1uF 50V, 20% 0603 X7R"
C6 C36: "Capacitor, 22uF 6.3V 20% X5R 0805"
C8: "CAP CER 1000PF 2KV 20% X7R 1210"
C9: "Capacitor, 4700pF, 2kV, 10%, X7R, 1812"
C14 C15 C45 C46 C47 C48: "CAP, CERM, 33pF, 50V, +/-5%, C0G/NP0, 0402"
C17 C21: "Capacitor, 4.7uF, 6.3V, 10% 0805, X5R"
C18: "Capacitor, 2.2uF, 16V, 10%, 0603, X5R"
C19 C20 C26 C32: "Capacitor, 1uF , X5R, 10V, 0402"
C29 C31 C33: "Capacitor, 0.1uF 16V, 10% 0402 X7R"
C30 C44: "CAP, CERM, 0.1uF, 25V, +/-5%, X7R, 0603"
C43: "Capacitor, 2.2uF 50V 10% X5R 0805"
D1 D2 D6 D7 D11: library part BAV99WT1G, "Diode, P-N, 70V, 0.2A, SOT-323"
D3: "Quad Channel High Speed ESD Protection Device, DCK0006A"
D4 D5 D16: "Diode, 5.6V ESD Suppressor 0402"
D8 D14: "LED, Green 565nm, Clear 0805 SMD"
D9: "Diode, Zener, 3.9V, 550mW, SMB"
D10: "Diode, Schottky, 200V, 1A, PowerDI123"
D12 D15: "LED AMBER CLEAR 0805 SMD"
D13: "LED, Red 630nm, Clear 0805 SMD"
FB1: library part MMZ1608B102C, "FERRITE CHIP 1000 OHM 300MA 0603"
FID1 FID2 FID3 FID4 FID5 FID6: "Fiducial mark.  There is nothing to buy or mount."
H1 H2 H3 H4 H5 H6: "Machine Screw, Round, #4-40 x 1/4, Nylon, Philips panhead"
J1: "Connector, RJ45 NO MAG, shielded THRU HOLE"
J2 J4 J6 J8: "Terminal Block, 4x1, 2.54mm, TH"
J3 J7: "Header, 2X5 2mm spacing"
J5: "Connector, USB micro AB Receptacle Reversed SMD"
J9: "CONN MICRO HS TERM STRP HDR 50 POS"
J10: "Header, 2mm, Low Profile 2x3"
L1: "Inductor 10uH, SMD 2.8x2.8mm, 0.5A, 0.47 Ohm"
LBL1: library part THT-14-423-10, "Thermal Transfer Printable Labels, 0.650\" W x 0.200\" H - 10,000 per roll"
R1 R2 R19 R59 R61: "Resistor, 2.2K OHM 1/10W 5% 0603 SMD"
R3 R60: "RES, 2.2k ohm, 5%, 0.063W, 0402"
R4 R6 R8 R23 R24 R30 R32 R37 R38 R40 R47 R48: "Resistor, 0 ohm, 1/10W, 5%, 0402"
R5: "RES, 1.0Meg ohm, 5%, 0.063W, 0402"
R7: "Resistor, 1M OHM 1/10W 5% 0603 SMD"
R9 R10 R11 R13: "Resistor, 49.9 OHM 1/10W 1% 0603 Thick"
R12 R56: "Resistor, 330 ohm, 1/10W, 5%, 0402"
R14 R15 R35 R36 R43 R46: "RES, 33 ohm, 5%, 0.063W, 0402"
R16: "Resistor, 1 OHM 1/10W 1% 0603, Thick"
R17 R18 R20 R33 R39 R44 R52 R54: "Resistor, 10k ohm, 1/10W, 5%, 0402 Thick Film"
R21: "Resistor, 1K Ohm, 1/10W, 5%, SMD, Thick"
R22 R49 R58 R62: "Resistor, 0 OHM 1/10W 0603 SMD"
R25 R45: "RES, 120 ohm, 1%, 0.25W, 1206"
R26 R27 R29 R34: "Resistor, 75 Ohm, 1/10W, 1%, SMD, Thick"
R28: "RES 1M OHM 5% 1206 TF"
R31: "Resistor, 51 ohm, 1/10W, 5%, 0402"
R41: "Resistor, 4.87K Ohm, 1/10W, 1%, SMD, Thick"
R42: "Resistor, 10K OHM 1/10W 5% 0603 SMD"
R50 R53 R55: "Resistor, 330 OHM 1/10W 5% 0603 SMD"
R51: "Resistor, 100K OHM 1/10W 5% 0603 Thick"
R57: "RES, 0.1 ohm, 1%, 0.1W, 0603"
SW1: "Switch, Tact 6mm SMT, 160gf"
T1: "TRANSFORMER, MDL, XFMR SGL ETHR LAN, SOIC-16"
TL1 TL2 TL3: "Terminal, Test Point Miniature Loop, Red, T-Hole"
TP1 TP2 TP3 TP4 TP5 TP6 TP7 TP8 TP9 TP10 TP11 TP12 TP13 TP14 TP15 TP16 TP17 TP18 TP19 TP20: library part TP-040_RND, "Test Point 40mil pad 20mil drill"
U1: library part SN65HVD3082ED, "IC TXRX RS485 3.3V ESD 8SOIC"
U2: "Stellaris MCU TM4C129XNCZAD 212 BGA, super"
U3: "Load Switch, 5.5V, SOT23-5, TPS2051BDBV"
U4: "CAN Transceiver with Fast Loop Times for Highly Loaded Networks, 85 mA, 5 V, -40 to 125 degC, 8-pin SOIC (D), Green (RoHS & no Sb/Br)"
U5: "Regulator, Step Down  3.3V, 0.5A"
U6: library part INA19NAIDBV, "IC, Current Shunt Monitor, -16V to 80V Common-Mode Range"
Y1: "Crystal, 25.00MHz 5.0x3.2mm SMT"
ZZ1 ZZ2 ZZ3: library part AssemblyNote
ZZ4: library part AssemblyNoteLabel

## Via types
v1: diameter 18, hole 8, TOP LAYER to BOTTOM LAYER, tented both sides, 415 vias

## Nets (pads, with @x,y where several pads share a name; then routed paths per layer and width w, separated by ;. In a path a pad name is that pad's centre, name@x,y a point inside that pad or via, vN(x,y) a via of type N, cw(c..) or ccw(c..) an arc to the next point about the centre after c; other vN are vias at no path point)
1_5V_PS: J9.44
3.3V: C1.1 C2.1 C5.1 C7.1 C10.1 C11.1 C13.1 C22.1 C23.1 C24.1 C25.1 C26.1 C27.1 C28.1 C29.1 C31.1 C33.1 C35.1 C36.1 C37.1 C38.1 C39.1 C40.1 C41.1 C44.1 D1.2 D2.2 D6.2 D7.2 D9.1 J7.1 R1.1 R2.1 R9.1 R10.1 R11.1 R12.1 R13.1 R16.2 R17.1 R18.1 R20.1 R30.2 R39.1 R44.2 R52.1 R54.1 R57.2 R59.1 R61.1 T1.2 T1.7 TL2.1 U1.8 U2.F3 U2.G10 U2.H9 U2.J8 U2.J9 U2.J10 U2.K7 U2.K8 U2.K11 U2.K12 U2.L10 U2.L11 U2.L12 U2.M11 U2.M12 U2.N16 U2.P10 U2.P17 U4.5 U6.3 U6.4 | length 2900.2
  TOP LAYER w8: v1(563.72,1301.29) 565.68,1301.29 U2.F3@583.98,1282.99 ; v1(587,1443) 597.5,1443 603.66,1436.84 U2.G10@603.66,1420.79 ; v1(608.72,1370.79) 623.35,1385.42 U2.H9@623.35,1401.1 U2.J9@643.03,1401.1 ; U2.J10@643.03,1420.79 U2.J9@643.03,1401.1 ; U2.K8@662.72,1381.42 U2.K7@662.72,1361.73 644.9,1361.73 643.82,1362.82 643.03,1363.6 U2.J8@643.03,1381.42 U2.J9@643.03,1401.1 ; U2.K11@662.72,1440.47 U2.K12@662.72,1460.16 ; U2.K12@663.03,1460.47 662.72,1460.79 U2.K12@662.72,1460.16 ; U2.L10@682.4,1420.79 U2.L11@682.4,1440.47 ; v1(716,1481) 715,1482 710.93,1482 706.72,1477.79 706.72,1464.79 U2.M12@702.09,1460.16 U2.L12@682.4,1460.16 ; v1(721.22,1558.79) 721.77,1558.23 U2.N16@721.77,1538.9 ; U2.P10@741.46,1420.79 721.77,1440.47 U2.M11@702.09,1440.47 U2.L11@682.4,1440.47 ; U2.P17@741.46,1558.58 747.56,1552.48 747.56,1552.03 754.59,1545 755.04,1545 760.25,1539.79 761,1539.79 v1@762.22,1539.79 ; U2.K12@662.72,1460.16 U2.L12@682.4,1460.16 ; U2.L11@682.4,1440.47 U2.L12@682.4,1460.16
  TOP LAYER w15: C2.1@316,2490.5 353.5,2490.5 381.22,2518.21 U1.8@381.22,2564.28 381.22,2612.78 370,2624 v1(358,2624) 319.5,2624 C1.1@316,2620.5 ; v1(908,1594) C5.1@949.5,1594 ; v1@981,1226 v1(982,1225) ; v1(1077,1604) 1087,1604 1107.5,1624.5 R10.1@1114,1624.5 ; R13.1@1200,1390.5 1238.5,1390.5 v1(1243,1395) ; v1(1239,1564) 1249.5,1574.5 R11.1@1277,1574.5 ; R9.1@1269.5,1639 1305,1639 v1(1308,1636) ; v1(1454,1969) T1.2@1506.52,1969 ; T1.7@1506.52,2219 1535,2219 1557,2197 v1(1557,2187) ; D6.2@1650.5,1566.41 1651.59,1566.41 v1(1681,1537) ; v1(1686,1297) 1699,1310 U4.5@1748.52,1310 ; v1(1790,1630) 1802.41,1617.59 D7.2@1824.5,1617.59 ; v1(1845,1530) 1856.62,1541.62 R12.1@1882,1541.62
  TOP LAYER w18: U6.4@1220,483 1220,463 1233,450 v1(1253,450) ; U6.3@1220,570 1220,605 v1(1224,609)
  BOTTOM LAYER w15: R52.1@230,741.62 v1@261.62,741.62 ; R18.1@230.38,824 266,824 v1(267,825) ; v1(236,1454) 236,1451 236.62,1450.38 R44.2@236.62,1425 ; C10.1@316,2490.5 316.5,2490 v1(354,2490) ; C7.1@316,2620.5 319.5,2624 v1(358,2624) ; C29.1@392.62,1445 v1(428.13,1445) ; C26.1@393.34,1496.79 v1(428.84,1496.79) ; C25.1@400.5,1552 429,1552 445.72,1535.28 v1(445.72,1516.68) ; C35.1@402,1193 v1(441,1193) ; D1.2@436.5,2723.59 v1@436.5,2754 ; v1(445,807) 477,807 477.62,807 R20.1@477,806.38 ; v1(448,893) 475,920 R17.1@475.62,920 ; R17.1@477,921.38 R17.1@475.62,920 ; R17.1@478.38,920 477,920 R17.1@475.62,920 ; v1(479,661) R54.1@479,694.38 ; v1(587,1443) 594.62,1435.38 C27.1@633,1435.38 ; v1@611.5,2643 D2.2@611.5,2672.41 ; v1(660,414) 660,396.5 R59.1@691,365.5 ; C28.1@693,1444.62 716,1467.62 v1(716,1481) ; R30.2@697.62,2076 736,2076 v1(737,2075) ; v1(766,184) 777,184 788.5,195.5 R61.1@788.5,226 ; v1(908,1594) 922.21,1579.79 C23.1@948.22,1579.79 ; C41.1@982,1193.5 v1(982,1225) ; R39.1@1056.34,1640.79 1077,1620.13 v1(1077,1604) ; v1(1239,1564) 1249.5,1574.5 C24.1@1277,1574.5 ; C22.1@1269.5,1639 1272.5,1636 v1(1308,1636) ; v1(1454,1969) C13.1@1497.5,1969 ; C11.1@1507,2220.5 1508.5,2219 1535,2219 1557,2197 v1(1557,2187) ; v1(1637,2552) 1638,2553 1638,2553.5 R1.1@1673,2588.5 ; v1(1815,2243) 1828.5,2229.5 R2.1@1828.5,2205
  BOTTOM LAYER w18: C40.1@660,1139.5 660,1174 v1(666,1180) ; C39.1@742,1142.5 v1(742,1183) ; C38.1@826,1148.5 v1(826,1183) ; v1(905.87,1387) C31.1@941.38,1387 ; C33.1@933.38,1301 933.38,1280.62 v1(944,1270) ; v1(1224,609) 1224,574.5 1225.5,573 C44.1@1225.5,560 R57.2@1225.5,490 1225.5,463.5 1239,450 v1(1253,450)
  other v1: 266,741 1241,1100 1340,1106 1241,1128 1340,1144 1259,1148 1285,1171 1315,1173 1370,1187 642,1361 761,1536 612,2643 436,2754
+5V: C21.1 C30.2 C43.1 D10.1 D11.3 R19.1 R21.1 R56.1 R62.1 TL3.1 U3.5 U4.3 U5.2 | length 2847.7
  TOP LAYER w8: 1415,678 U5.2@1415,708
  TOP LAYER w15: v1(215,1603) 215,1603.4 214.8,1603.2 214.59,1602.99 U3.5@215.3,1575.4 ; v1(1391,632) 1408.64,649.64 v1(1408.64,652.36) 1415,658.73 1415,678 ; v1(1456,475) 1457,475 1466,484 1466,506 R21.1@1474,514 1493,495 1493,479 1489,475 v1(1489,473) ; v1(1507.5,1353.5) 1513.99,1360 U4.3@1563.48,1360 ; v1(1555,669) R19.1@1555,711.5 1555.5,712 v1(1597,712)
  L3_PWR-PLANE w50: v1(215,1603) 139,1603 103,1567 103,1403 324,1182 324,1107 220,1003 220,637 299,558 299,157 357.5,98.5 358,98 360,100 v1(360,101)
  BOTTOM LAYER w15: v1(215,1603) 215,1615 231,1631 C21.1@276.54,1631 ; TL3.1@1686,685 1691,690 R56.1@1800.38,690
  BOTTOM LAYER w20: v1(1391,632) 1391,634.73 v1(1408.64,652.36) C43.1@1408.64,706.1 ; v1(1507.5,1353.5) C30.2@1566,1353.5
  BOTTOM LAYER w25: C30.2@1566,1353.5 1566,1234 1592,1208 1592,1034 v1(1616,1010)
  other v1: 392,100 419,101 447,101 1601,985 1631,985 1581,1010 1646,1010
+VBUS: C17.1 J5.1 R36.1 U3.1 | length 669.9
  TOP LAYER w14: J5.1@176.32,1898.82 225.18,1898.82 272,1852 292,1852 v1(307,1837)
  TOP LAYER w15: U3.1@128.7,1575.4 145.4,1575.4 214,1644 262,1644 290,1672 290,1820 v1(307,1837)
  BOTTOM LAYER w14: C17.1@307,1781.46 C17.1@307,1786.46 v1(307,1837)
  BOTTOM LAYER w15: C17.1@307,1781.46 309.5,1783.96 309.54,1784 315.91,1777.62 R36.1@388,1777.62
